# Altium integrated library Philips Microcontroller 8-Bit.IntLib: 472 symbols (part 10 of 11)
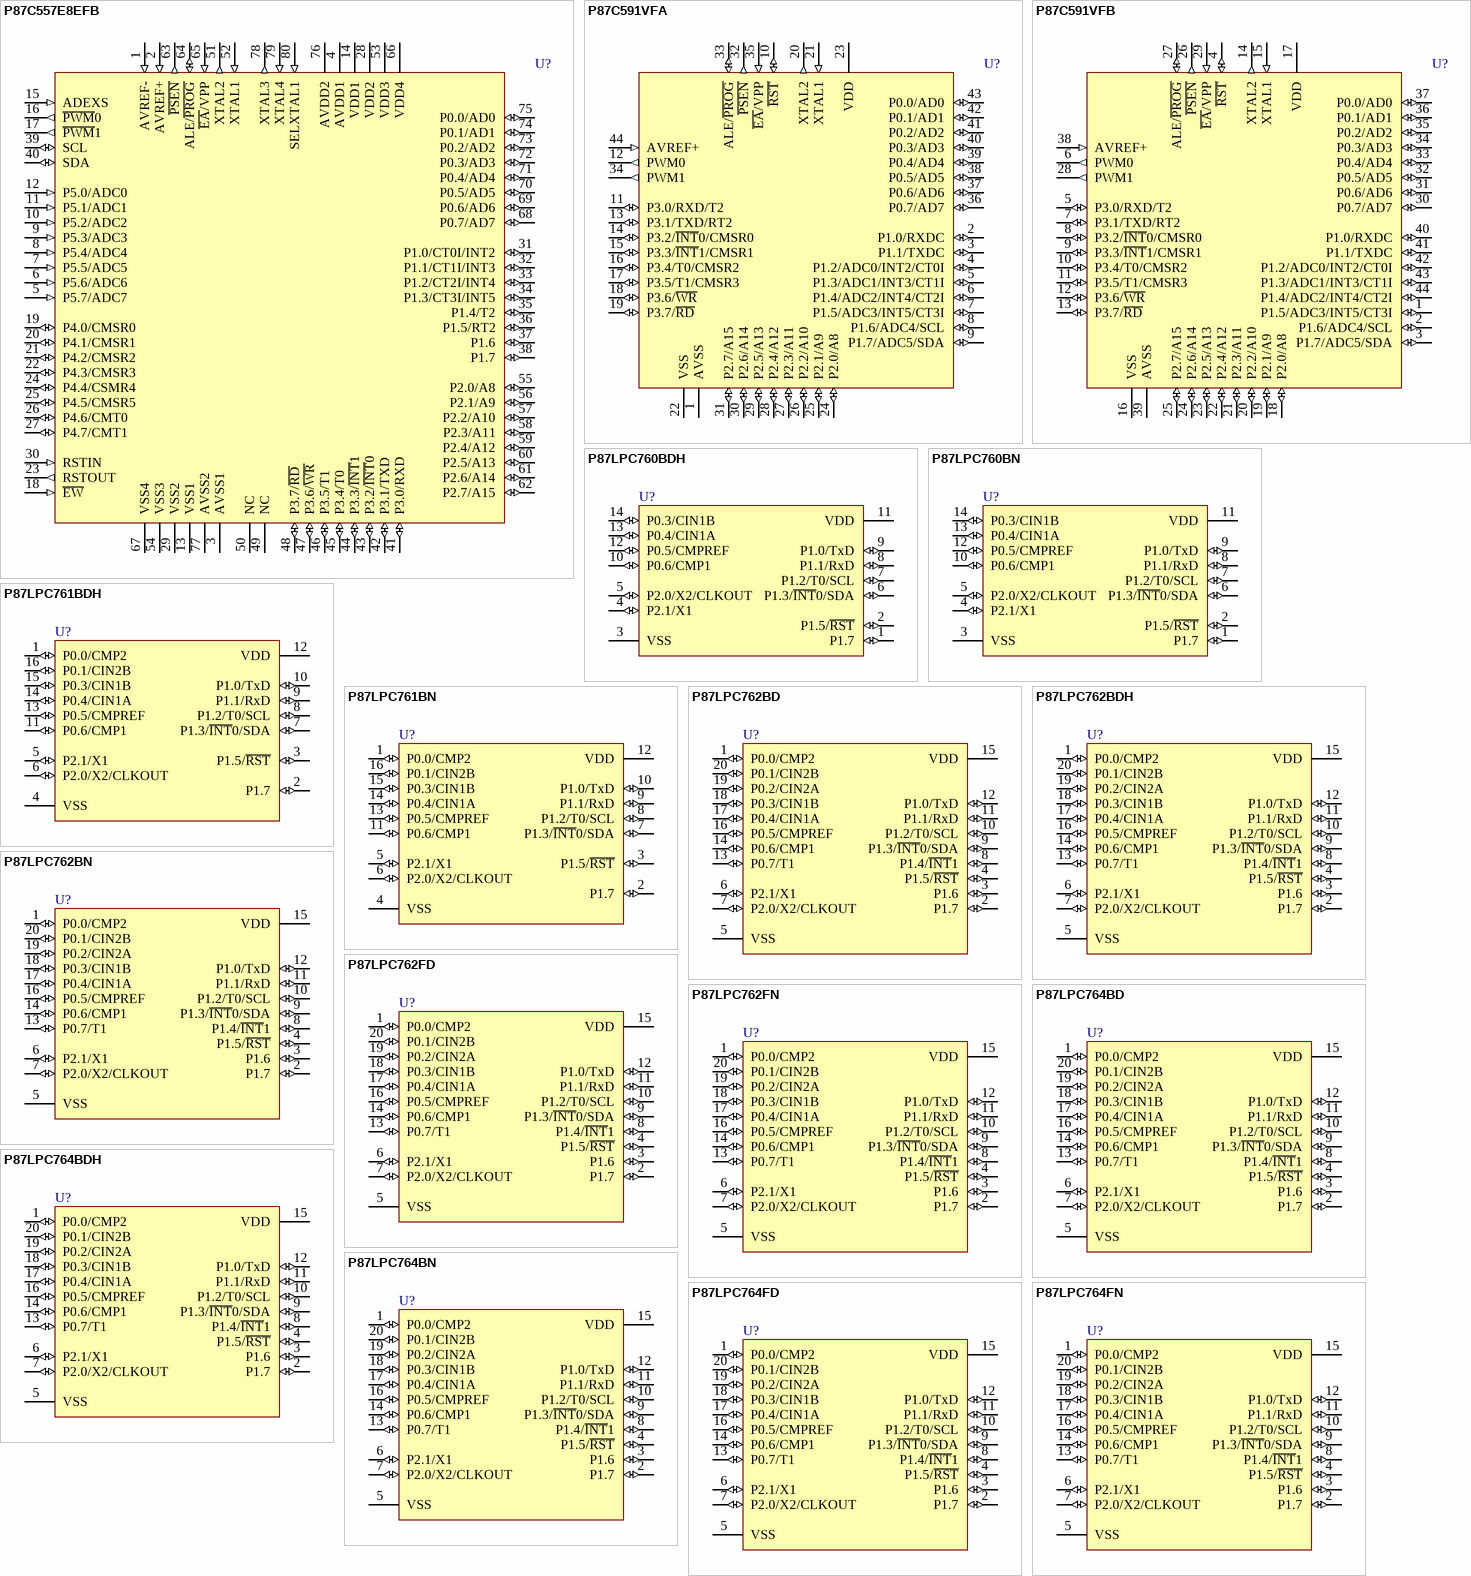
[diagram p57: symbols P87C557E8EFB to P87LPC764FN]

## P87LPC762BN
designator U?
Low Power, Low Price, Low Pin Count (20 pin) Microcontroller with 2 kB OTP
footprint SOT146-1 (DIP; 20 Leads; Row Spacing 7.62 mm; Pitch 2.54 mm)
pins: 1 P0.0/CMP2 (io), 2 P1.7 (io), 3 P1.6 (io), 4 P1.5/~{RST} (io), 5 VSS (power), 6 P2.1/X1 (io), 7 P2.0/X2/CLKOUT (io), 8 P1.4/~{INT}1 (io), 9 P1.3/~{INT}0/SDA (io), 10 P1.2/T0/SCL (io), 11 P1.1/RxD (io), 12 P1.0/TxD (io), 13 P0.7/T1 (io), 14 P0.6/CMP1 (io), 15 VDD (power), 16 P0.5/CMPREF (io), 17 P0.4/CIN1A (io), 18 P0.3/CIN1B (io), 19 P0.2/CIN2A (io), 20 P0.1/CIN2B (io)

## P87LPC762FD
designator U?
Low Power, Low Price, Low Pin Count (20 pin) Microcontroller with 2 kB OTP
footprint SOT163-1_N (SOIC, 20-Leads, Body 12.8x7.5mm, Pitch 1.27mm, IPC Medium Density)
footprint SOT163-1_L (SOIC, 20-Leads, Body 12.8x7.5mm, Pitch 1.27mm, IPC High Density)
footprint SOT163-1_M (SOIC, 20-Leads, Body 12.8x7.5mm, Pitch 1.27mm, IPC Low Density)
pins: 1 P0.0/CMP2 (io), 2 P1.7 (io), 3 P1.6 (io), 4 P1.5/~{RST} (io), 5 VSS (power), 6 P2.1/X1 (io), 7 P2.0/X2/CLKOUT (io), 8 P1.4/~{INT}1 (io), 9 P1.3/~{INT}0/SDA (io), 10 P1.2/T0/SCL (io), 11 P1.1/RxD (io), 12 P1.0/TxD (io), 13 P0.7/T1 (io), 14 P0.6/CMP1 (io), 15 VDD (power), 16 P0.5/CMPREF (io), 17 P0.4/CIN1A (io), 18 P0.3/CIN1B (io), 19 P0.2/CIN2A (io), 20 P0.1/CIN2B (io)

## P87LPC762FN
designator U?
Low Power, Low Price, Low Pin Count (20 pin) Microcontroller with 2 kB OTP
footprint SOT146-1 (DIP; 20 Leads; Row Spacing 7.62 mm; Pitch 2.54 mm)
pins: 1 P0.0/CMP2 (io), 2 P1.7 (io), 3 P1.6 (io), 4 P1.5/~{RST} (io), 5 VSS (power), 6 P2.1/X1 (io), 7 P2.0/X2/CLKOUT (io), 8 P1.4/~{INT}1 (io), 9 P1.3/~{INT}0/SDA (io), 10 P1.2/T0/SCL (io), 11 P1.1/RxD (io), 12 P1.0/TxD (io), 13 P0.7/T1 (io), 14 P0.6/CMP1 (io), 15 VDD (power), 16 P0.5/CMPREF (io), 17 P0.4/CIN1A (io), 18 P0.3/CIN1B (io), 19 P0.2/CIN2A (io), 20 P0.1/CIN2B (io)

## P87LPC764BD
designator U?
Low Power, Low Price, Low Pin Count (20 pin) Microcontroller with 4 kB OTP
footprint SOT163-1_N (SOIC, 20-Leads, Body 12.8x7.5mm, Pitch 1.27mm, IPC Medium Density)
footprint SOT163-1_L (SOIC, 20-Leads, Body 12.8x7.5mm, Pitch 1.27mm, IPC High Density)
footprint SOT163-1_M (SOIC, 20-Leads, Body 12.8x7.5mm, Pitch 1.27mm, IPC Low Density)
pins: 1 P0.0/CMP2 (io), 2 P1.7 (io), 3 P1.6 (io), 4 P1.5/~{RST} (io), 5 VSS (power), 6 P2.1/X1 (io), 7 P2.0/X2/CLKOUT (io), 8 P1.4/~{INT}1 (io), 9 P1.3/~{INT}0/SDA (io), 10 P1.2/T0/SCL (io), 11 P1.1/RxD (io), 12 P1.0/TxD (io), 13 P0.7/T1 (io), 14 P0.6/CMP1 (io), 15 VDD (power), 16 P0.5/CMPREF (io), 17 P0.4/CIN1A (io), 18 P0.3/CIN1B (io), 19 P0.2/CIN2A (io), 20 P0.1/CIN2B (io)

## P87LPC764BDH
designator U?
Low Power, Low Price, Low Pin Count (20 pin) Microcontroller with 4 kB OTP
footprint SOT360-1 (Shrink Small Outline; 20 Leads; Body Width 4.4 mm; Pitch 0.65 mm)
pins: 1 P0.0/CMP2 (io), 2 P1.7 (io), 3 P1.6 (io), 4 P1.5/~{RST} (io), 5 VSS (power), 6 P2.1/X1 (io), 7 P2.0/X2/CLKOUT (io), 8 P1.4/~{INT}1 (io), 9 P1.3/~{INT}0/SDA (io), 10 P1.2/T0/SCL (io), 11 P1.1/RxD (io), 12 P1.0/TxD (io), 13 P0.7/T1 (io), 14 P0.6/CMP1 (io), 15 VDD (power), 16 P0.5/CMPREF (io), 17 P0.4/CIN1A (io), 18 P0.3/CIN1B (io), 19 P0.2/CIN2A (io), 20 P0.1/CIN2B (io)

## P87LPC764BN
designator U?
Low Power, Low Price, Low Pin Count (20 pin) Microcontroller with 4 kB OTP
footprint SOT146-1 (DIP; 20 Leads; Row Spacing 7.62 mm; Pitch 2.54 mm)
pins: 1 P0.0/CMP2 (io), 2 P1.7 (io), 3 P1.6 (io), 4 P1.5/~{RST} (io), 5 VSS (power), 6 P2.1/X1 (io), 7 P2.0/X2/CLKOUT (io), 8 P1.4/~{INT}1 (io), 9 P1.3/~{INT}0/SDA (io), 10 P1.2/T0/SCL (io), 11 P1.1/RxD (io), 12 P1.0/TxD (io), 13 P0.7/T1 (io), 14 P0.6/CMP1 (io), 15 VDD (power), 16 P0.5/CMPREF (io), 17 P0.4/CIN1A (io), 18 P0.3/CIN1B (io), 19 P0.2/CIN2A (io), 20 P0.1/CIN2B (io)

## P87LPC764FD
designator U?
Low Power, Low Price, Low Pin Count (20 pin) Microcontroller with 4 kB OTP
footprint SOT163-1_N (SOIC, 20-Leads, Body 12.8x7.5mm, Pitch 1.27mm, IPC Medium Density)
footprint SOT163-1_L (SOIC, 20-Leads, Body 12.8x7.5mm, Pitch 1.27mm, IPC High Density)
footprint SOT163-1_M (SOIC, 20-Leads, Body 12.8x7.5mm, Pitch 1.27mm, IPC Low Density)
pins: 1 P0.0/CMP2 (io), 2 P1.7 (io), 3 P1.6 (io), 4 P1.5/~{RST} (io), 5 VSS (power), 6 P2.1/X1 (io), 7 P2.0/X2/CLKOUT (io), 8 P1.4/~{INT}1 (io), 9 P1.3/~{INT}0/SDA (io), 10 P1.2/T0/SCL (io), 11 P1.1/RxD (io), 12 P1.0/TxD (io), 13 P0.7/T1 (io), 14 P0.6/CMP1 (io), 15 VDD (power), 16 P0.5/CMPREF (io), 17 P0.4/CIN1A (io), 18 P0.3/CIN1B (io), 19 P0.2/CIN2A (io), 20 P0.1/CIN2B (io)

## P87LPC764FN
designator U?
Low Power, Low Price, Low Pin Count (20 pin) Microcontroller with 4 kB OTP
footprint SOT146-1 (DIP; 20 Leads; Row Spacing 7.62 mm; Pitch 2.54 mm)
pins: 1 P0.0/CMP2 (io), 2 P1.7 (io), 3 P1.6 (io), 4 P1.5/~{RST} (io), 5 VSS (power), 6 P2.1/X1 (io), 7 P2.0/X2/CLKOUT (io), 8 P1.4/~{INT}1 (io), 9 P1.3/~{INT}0/SDA (io), 10 P1.2/T0/SCL (io), 11 P1.1/RxD (io), 12 P1.0/TxD (io), 13 P0.7/T1 (io), 14 P0.6/CMP1 (io), 15 VDD (power), 16 P0.5/CMPREF (io), 17 P0.4/CIN1A (io), 18 P0.3/CIN1B (io), 19 P0.2/CIN2A (io), 20 P0.1/CIN2B (io)

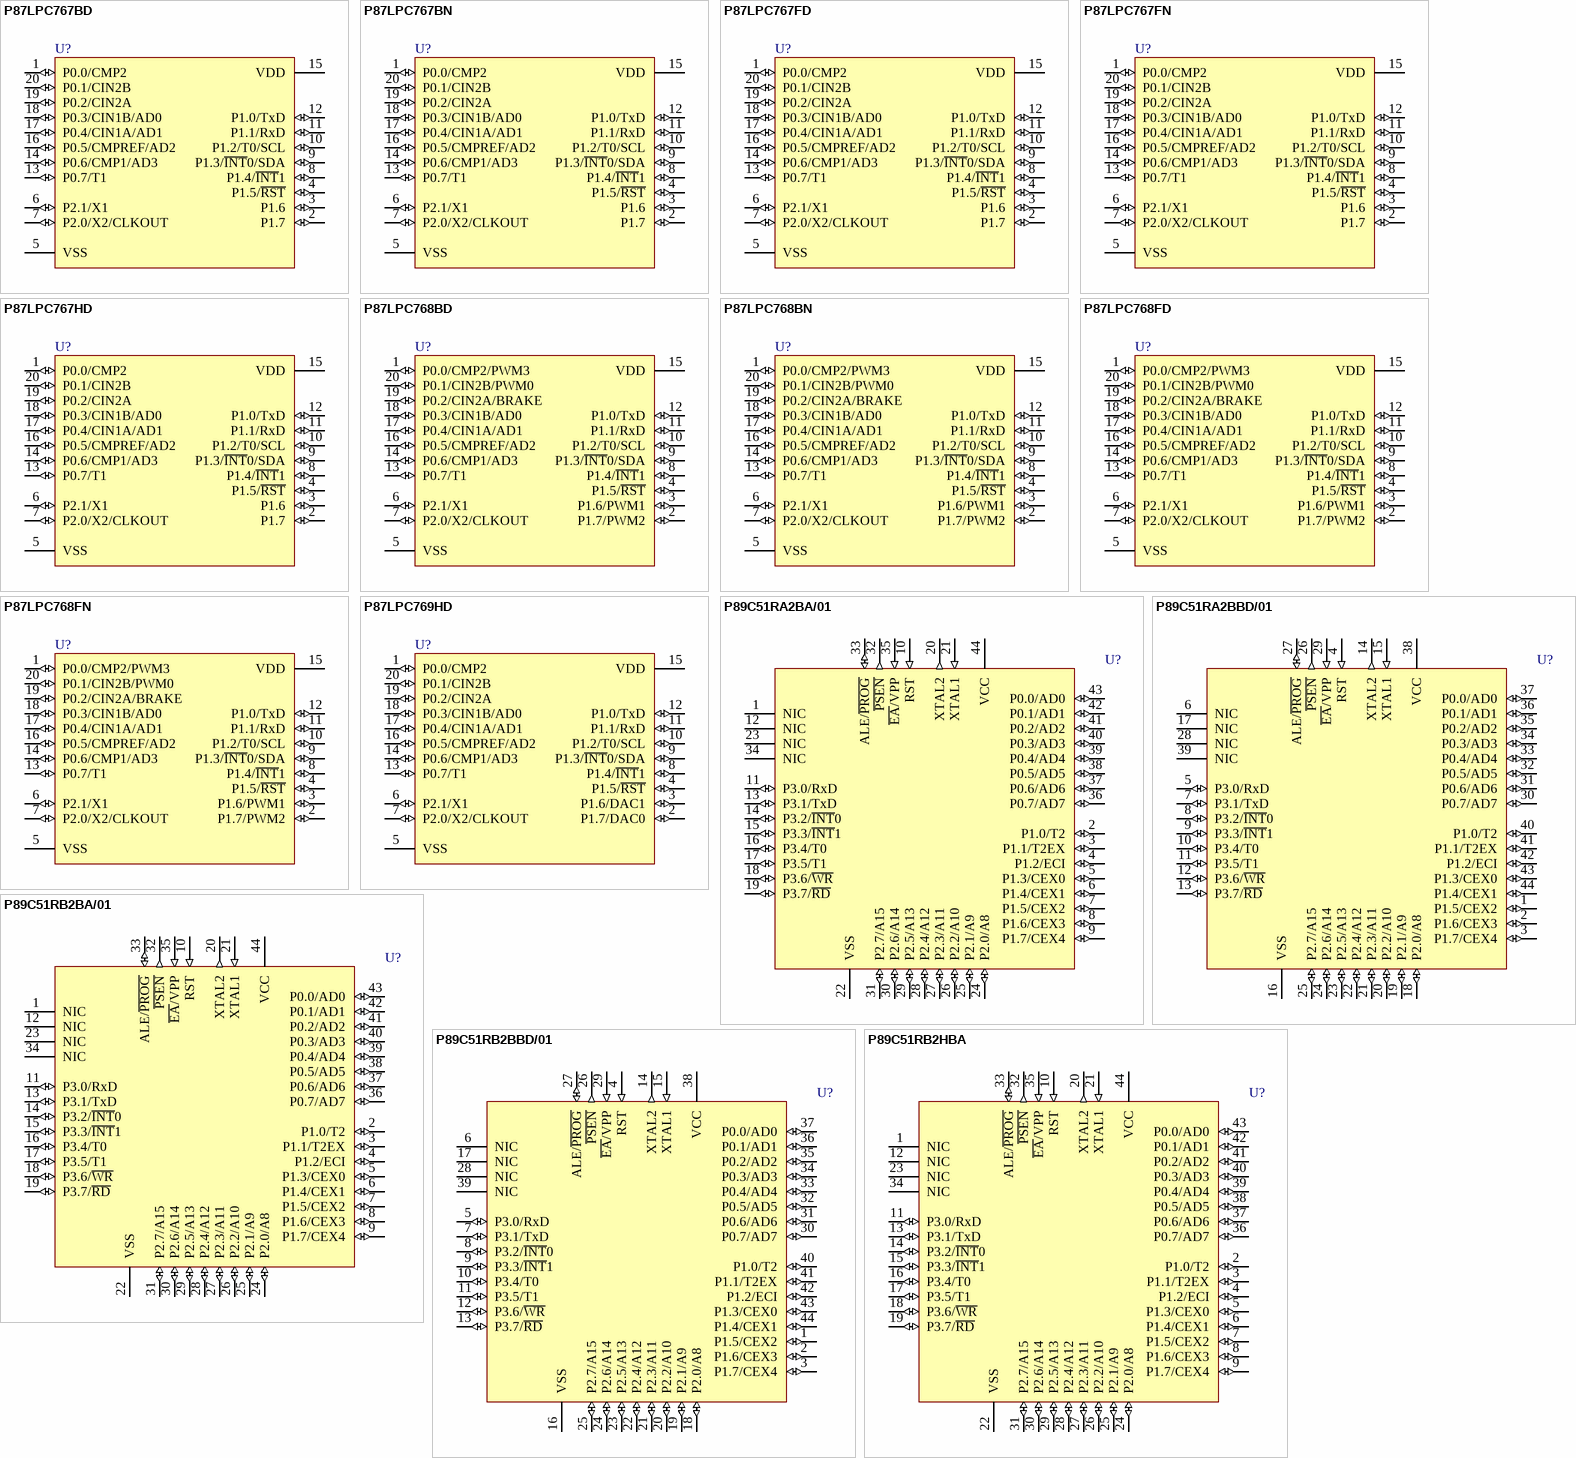
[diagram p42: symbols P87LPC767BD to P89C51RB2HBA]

## P87LPC767BD
designator U?
Low Power, Low Price, Low Pin Count (20 pin) Microcontroller with 4 kB OTP and 8-Bit A/D Converter
footprint SOT163-1_N (SOIC, 20-Leads, Body 12.8x7.5mm, Pitch 1.27mm, IPC Medium Density)
footprint SOT163-1_L (SOIC, 20-Leads, Body 12.8x7.5mm, Pitch 1.27mm, IPC High Density)
footprint SOT163-1_M (SOIC, 20-Leads, Body 12.8x7.5mm, Pitch 1.27mm, IPC Low Density)
pins: 1 P0.0/CMP2 (io), 2 P1.7 (io), 3 P1.6 (io), 4 P1.5/~{RST} (io), 5 VSS (power), 6 P2.1/X1 (io), 7 P2.0/X2/CLKOUT (io), 8 P1.4/~{INT}1 (io), 9 P1.3/~{INT}0/SDA (io), 10 P1.2/T0/SCL (io), 11 P1.1/RxD (io), 12 P1.0/TxD (io), 13 P0.7/T1 (io), 14 P0.6/CMP1/AD3 (io), 15 VDD (power), 16 P0.5/CMPREF/AD2 (io), 17 P0.4/CIN1A/AD1 (io), 18 P0.3/CIN1B/AD0 (io), 19 P0.2/CIN2A (io), 20 P0.1/CIN2B (io)

## P87LPC767BN
designator U?
Low Power, Low Price, Low Pin Count (20 pin) Microcontroller with 4 kB OTP and 8-Bit A/D Converter
footprint SOT146-1 (DIP; 20 Leads; Row Spacing 7.62 mm; Pitch 2.54 mm)
pins: 1 P0.0/CMP2 (io), 2 P1.7 (io), 3 P1.6 (io), 4 P1.5/~{RST} (io), 5 VSS (power), 6 P2.1/X1 (io), 7 P2.0/X2/CLKOUT (io), 8 P1.4/~{INT}1 (io), 9 P1.3/~{INT}0/SDA (io), 10 P1.2/T0/SCL (io), 11 P1.1/RxD (io), 12 P1.0/TxD (io), 13 P0.7/T1 (io), 14 P0.6/CMP1/AD3 (io), 15 VDD (power), 16 P0.5/CMPREF/AD2 (io), 17 P0.4/CIN1A/AD1 (io), 18 P0.3/CIN1B/AD0 (io), 19 P0.2/CIN2A (io), 20 P0.1/CIN2B (io)

## P87LPC767FD
designator U?
Low Power, Low Price, Low Pin Count (20 pin) Microcontroller with 4 kB OTP and 8-Bit A/D Converter
footprint SOT163-1_N (SOIC, 20-Leads, Body 12.8x7.5mm, Pitch 1.27mm, IPC Medium Density)
footprint SOT163-1_L (SOIC, 20-Leads, Body 12.8x7.5mm, Pitch 1.27mm, IPC High Density)
footprint SOT163-1_M (SOIC, 20-Leads, Body 12.8x7.5mm, Pitch 1.27mm, IPC Low Density)
pins: 1 P0.0/CMP2 (io), 2 P1.7 (io), 3 P1.6 (io), 4 P1.5/~{RST} (io), 5 VSS (power), 6 P2.1/X1 (io), 7 P2.0/X2/CLKOUT (io), 8 P1.4/~{INT}1 (io), 9 P1.3/~{INT}0/SDA (io), 10 P1.2/T0/SCL (io), 11 P1.1/RxD (io), 12 P1.0/TxD (io), 13 P0.7/T1 (io), 14 P0.6/CMP1/AD3 (io), 15 VDD (power), 16 P0.5/CMPREF/AD2 (io), 17 P0.4/CIN1A/AD1 (io), 18 P0.3/CIN1B/AD0 (io), 19 P0.2/CIN2A (io), 20 P0.1/CIN2B (io)

## P87LPC767FN
designator U?
Low Power, Low Price, Low Pin Count (20 pin) Microcontroller with 4 kB OTP and 8-Bit A/D Converter
footprint SOT146-1 (DIP; 20 Leads; Row Spacing 7.62 mm; Pitch 2.54 mm)
pins: 1 P0.0/CMP2 (io), 2 P1.7 (io), 3 P1.6 (io), 4 P1.5/~{RST} (io), 5 VSS (power), 6 P2.1/X1 (io), 7 P2.0/X2/CLKOUT (io), 8 P1.4/~{INT}1 (io), 9 P1.3/~{INT}0/SDA (io), 10 P1.2/T0/SCL (io), 11 P1.1/RxD (io), 12 P1.0/TxD (io), 13 P0.7/T1 (io), 14 P0.6/CMP1/AD3 (io), 15 VDD (power), 16 P0.5/CMPREF/AD2 (io), 17 P0.4/CIN1A/AD1 (io), 18 P0.3/CIN1B/AD0 (io), 19 P0.2/CIN2A (io), 20 P0.1/CIN2B (io)

## P87LPC767HD
designator U?
Low Power, Low Price, Low Pin Count (20 pin) Microcontroller with 4 kB OTP and 8-Bit A/D Converter
footprint SOT163-1_N (SOIC, 20-Leads, Body 12.8x7.5mm, Pitch 1.27mm, IPC Medium Density)
footprint SOT163-1_L (SOIC, 20-Leads, Body 12.8x7.5mm, Pitch 1.27mm, IPC High Density)
footprint SOT163-1_M (SOIC, 20-Leads, Body 12.8x7.5mm, Pitch 1.27mm, IPC Low Density)
pins: 1 P0.0/CMP2 (io), 2 P1.7 (io), 3 P1.6 (io), 4 P1.5/~{RST} (io), 5 VSS (power), 6 P2.1/X1 (io), 7 P2.0/X2/CLKOUT (io), 8 P1.4/~{INT}1 (io), 9 P1.3/~{INT}0/SDA (io), 10 P1.2/T0/SCL (io), 11 P1.1/RxD (io), 12 P1.0/TxD (io), 13 P0.7/T1 (io), 14 P0.6/CMP1/AD3 (io), 15 VDD (power), 16 P0.5/CMPREF/AD2 (io), 17 P0.4/CIN1A/AD1 (io), 18 P0.3/CIN1B/AD0 (io), 19 P0.2/CIN2A (io), 20 P0.1/CIN2B (io)

## P87LPC768BD
designator U?
Low Power, Low Price, Low Pin Count (20 pin) Microcontroller with 4 kB OTP 8-Bit A/D, PWM
footprint SOT163-1_N (SOIC, 20-Leads, Body 12.8x7.5mm, Pitch 1.27mm, IPC Medium Density)
footprint SOT163-1_L (SOIC, 20-Leads, Body 12.8x7.5mm, Pitch 1.27mm, IPC High Density)
footprint SOT163-1_M (SOIC, 20-Leads, Body 12.8x7.5mm, Pitch 1.27mm, IPC Low Density)
pins: 1 P0.0/CMP2/PWM3 (io), 2 P1.7/PWM2 (io), 3 P1.6/PWM1 (io), 4 P1.5/~{RST} (io), 5 VSS (power), 6 P2.1/X1 (io), 7 P2.0/X2/CLKOUT (io), 8 P1.4/~{INT}1 (io), 9 P1.3/~{INT}0/SDA (io), 10 P1.2/T0/SCL (io), 11 P1.1/RxD (io), 12 P1.0/TxD (io), 13 P0.7/T1 (io), 14 P0.6/CMP1/AD3 (io), 15 VDD (power), 16 P0.5/CMPREF/AD2 (io), 17 P0.4/CIN1A/AD1 (io), 18 P0.3/CIN1B/AD0 (io), 19 P0.2/CIN2A/BRAKE (io), 20 P0.1/CIN2B/PWM0 (io)

## P87LPC768BN
designator U?
Low Power, Low Price, Low Pin Count (20 pin) Microcontroller with 4 kB OTP 8-Bit A/D, PWM
footprint SOT146-1 (DIP; 20 Leads; Row Spacing 7.62 mm; Pitch 2.54 mm)
pins: 1 P0.0/CMP2/PWM3 (io), 2 P1.7/PWM2 (io), 3 P1.6/PWM1 (io), 4 P1.5/~{RST} (io), 5 VSS (power), 6 P2.1/X1 (io), 7 P2.0/X2/CLKOUT (io), 8 P1.4/~{INT}1 (io), 9 P1.3/~{INT}0/SDA (io), 10 P1.2/T0/SCL (io), 11 P1.1/RxD (io), 12 P1.0/TxD (io), 13 P0.7/T1 (io), 14 P0.6/CMP1/AD3 (io), 15 VDD (power), 16 P0.5/CMPREF/AD2 (io), 17 P0.4/CIN1A/AD1 (io), 18 P0.3/CIN1B/AD0 (io), 19 P0.2/CIN2A/BRAKE (io), 20 P0.1/CIN2B/PWM0 (io)

## P87LPC768FD
designator U?
Low Power, Low Price, Low Pin Count (20 pin) Microcontroller with 4 kB OTP 8-Bit A/D, PWM
footprint SOT163-1_N (SOIC, 20-Leads, Body 12.8x7.5mm, Pitch 1.27mm, IPC Medium Density)
footprint SOT163-1_L (SOIC, 20-Leads, Body 12.8x7.5mm, Pitch 1.27mm, IPC High Density)
footprint SOT163-1_M (SOIC, 20-Leads, Body 12.8x7.5mm, Pitch 1.27mm, IPC Low Density)
pins: 1 P0.0/CMP2/PWM3 (io), 2 P1.7/PWM2 (io), 3 P1.6/PWM1 (io), 4 P1.5/~{RST} (io), 5 VSS (power), 6 P2.1/X1 (io), 7 P2.0/X2/CLKOUT (io), 8 P1.4/~{INT}1 (io), 9 P1.3/~{INT}0/SDA (io), 10 P1.2/T0/SCL (io), 11 P1.1/RxD (io), 12 P1.0/TxD (io), 13 P0.7/T1 (io), 14 P0.6/CMP1/AD3 (io), 15 VDD (power), 16 P0.5/CMPREF/AD2 (io), 17 P0.4/CIN1A/AD1 (io), 18 P0.3/CIN1B/AD0 (io), 19 P0.2/CIN2A/BRAKE (io), 20 P0.1/CIN2B/PWM0 (io)

## P87LPC768FN
designator U?
Low Power, Low Price, Low Pin Count (20 pin) Microcontroller with 4 kB OTP 8-Bit A/D, PWM
footprint SOT146-1 (DIP; 20 Leads; Row Spacing 7.62 mm; Pitch 2.54 mm)
pins: 1 P0.0/CMP2/PWM3 (io), 2 P1.7/PWM2 (io), 3 P1.6/PWM1 (io), 4 P1.5/~{RST} (io), 5 VSS (power), 6 P2.1/X1 (io), 7 P2.0/X2/CLKOUT (io), 8 P1.4/~{INT}1 (io), 9 P1.3/~{INT}0/SDA (io), 10 P1.2/T0/SCL (io), 11 P1.1/RxD (io), 12 P1.0/TxD (io), 13 P0.7/T1 (io), 14 P0.6/CMP1/AD3 (io), 15 VDD (power), 16 P0.5/CMPREF/AD2 (io), 17 P0.4/CIN1A/AD1 (io), 18 P0.3/CIN1B/AD0 (io), 19 P0.2/CIN2A/BRAKE (io), 20 P0.1/CIN2B/PWM0 (io)

## P87LPC769HD
designator U?
Low Power, Low Price, Low Pin Count (20 pin) Microcontroller with 4 kB OTP 8-Bit A/D, and DAC
footprint SOT163-1_N (SOIC, 20-Leads, Body 12.8x7.5mm, Pitch 1.27mm, IPC Medium Density)
footprint SOT163-1_L (SOIC, 20-Leads, Body 12.8x7.5mm, Pitch 1.27mm, IPC High Density)
footprint SOT163-1_M (SOIC, 20-Leads, Body 12.8x7.5mm, Pitch 1.27mm, IPC Low Density)
pins: 1 P0.0/CMP2 (io), 2 P1.7/DAC0 (io), 3 P1.6/DAC1 (io), 4 P1.5/~{RST} (io), 5 VSS (power), 6 P2.1/X1 (io), 7 P2.0/X2/CLKOUT (io), 8 P1.4/~{INT}1 (io), 9 P1.3/~{INT}0/SDA (io), 10 P1.2/T0/SCL (io), 11 P1.1/RxD (io), 12 P1.0/TxD (io), 13 P0.7/T1 (io), 14 P0.6/CMP1/AD3 (io), 15 VDD (power), 16 P0.5/CMPREF/AD2 (io), 17 P0.4/CIN1A/AD1 (io), 18 P0.3/CIN1B/AD0 (io), 19 P0.2/CIN2A (io), 20 P0.1/CIN2B (io)

## P89C51RA2BA/01
designator U?
80C51 8-Bit Flash Microcontroller Family, 8 kB ISP/IAP Flash with 512 B RAM.
footprint SOT187-2_N (Leaded Chip Carrier, 44-Leads, Body 16.6x16.6mm, Pitch 1.27mm, IPC Medium Density)
footprint SOT187-2_L (Leaded Chip Carrier, 44-Leads, Body 16.6x16.6mm, Pitch 1.27mm, IPC High Density)
footprint SOT187-2_M (Leaded Chip Carrier, 44-Leads, Body 16.6x16.6mm, Pitch 1.27mm, IPC Low Density)
pins: 1 NIC, 2 P1.0/T2 (io), 3 P1.1/T2EX (io), 4 P1.2/ECI (io), 5 P1.3/CEX0 (io), 6 P1.4/CEX1 (io), 7 P1.5/CEX2 (io), 8 P1.6/CEX3 (io), 9 P1.7/CEX4 (io), 10 RST (in), 11 P3.0/RxD (io), 12 NIC, 13 P3.1/TxD (io), 14 P3.2/~{INT}0 (io), 15 P3.3/~{INT}1 (io), 16 P3.4/T0 (io), 17 P3.5/T1 (io), 18 P3.6/~{WR} (io), 19 P3.7/~{RD} (io), 20 XTAL2 (out), 21 XTAL1 (in), 22 VSS (power), 23 NIC, 24 P2.0/A8 (io), 25 P2.1/A9 (io), 26 P2.2/A10 (io), 27 P2.3/A11 (io), 28 P2.4/A12 (io), 29 P2.5/A13 (io), 30 P2.6/A14 (io), 31 P2.7/A15 (io), 32 ~{PSEN} (out), 33 ALE/~{PROG} (io), 34 NIC, 35 ~{EA}/VPP (in), 36 P0.7/AD7 (io), 37 P0.6/AD6 (io), 38 P0.5/AD5 (io), 39 P0.4/AD4 (io), 40 P0.3/AD3 (io), 41 P0.2/AD2 (io), 42 P0.1/AD1 (io), 43 P0.0/AD0 (io), 44 VCC (power)

## P89C51RA2BBD/01
designator U?
80C51 8-Bit Flash Microcontroller Family, 8 kB ISP/IAP Flash with 512 B RAM.
footprint SOT389-1_N (Thin QFP, 44-Leads, Body 10x10mm, Pitch 0.8mm, IPC Medium Density)
footprint SOT389-1_L (Thin QFP, 44-Leads, Body 10x10mm, Pitch 0.8mm, IPC High Density)
footprint SOT389-1_M (Thin QFP, 44-Leads, Body 10x10mm, Pitch 0.8mm, IPC Low Density)
pins: 1 P1.5/CEX2 (io), 2 P1.6/CEX3 (io), 3 P1.7/CEX4 (io), 4 RST (in), 5 P3.0/RxD (io), 6 NIC, 7 P3.1/TxD (io), 8 P3.2/~{INT}0 (io), 9 P3.3/~{INT}1 (io), 10 P3.4/T0 (io), 11 P3.5/T1 (io), 12 P3.6/~{WR} (io), 13 P3.7/~{RD} (io), 14 XTAL2 (out), 15 XTAL1 (in), 16 VSS (power), 17 NIC, 18 P2.0/A8 (io), 19 P2.1/A9 (io), 20 P2.2/A10 (io), 21 P2.3/A11 (io), 22 P2.4/A12 (io), 23 P2.5/A13 (io), 24 P2.6/A14 (io), 25 P2.7/A15 (io), 26 ~{PSEN} (out), 27 ALE/~{PROG} (io), 28 NIC, 29 ~{EA}/VPP (in), 30 P0.7/AD7 (io), 31 P0.6/AD6 (io), 32 P0.5/AD5 (io), 33 P0.4/AD4 (io), 34 P0.3/AD3 (io), 35 P0.2/AD2 (io), 36 P0.1/AD1 (io), 37 P0.0/AD0 (io), 38 VCC (power), 39 NIC, 40 P1.0/T2 (io), 41 P1.1/T2EX (io), 42 P1.2/ECI (io), 43 P1.3/CEX0 (io), 44 P1.4/CEX1 (io)

## P89C51RB2BA/01
designator U?
80C51 8-Bit Flash Microcontroller Family, 16 kB ISP/IAP Flash with 512 B RAM.
footprint SOT187-2_N (Leaded Chip Carrier, 44-Leads, Body 16.6x16.6mm, Pitch 1.27mm, IPC Medium Density)
footprint SOT187-2_L (Leaded Chip Carrier, 44-Leads, Body 16.6x16.6mm, Pitch 1.27mm, IPC High Density)
footprint SOT187-2_M (Leaded Chip Carrier, 44-Leads, Body 16.6x16.6mm, Pitch 1.27mm, IPC Low Density)
pins: 1 NIC, 2 P1.0/T2 (io), 3 P1.1/T2EX (io), 4 P1.2/ECI (io), 5 P1.3/CEX0 (io), 6 P1.4/CEX1 (io), 7 P1.5/CEX2 (io), 8 P1.6/CEX3 (io), 9 P1.7/CEX4 (io), 10 RST (in), 11 P3.0/RxD (io), 12 NIC, 13 P3.1/TxD (io), 14 P3.2/~{INT}0 (io), 15 P3.3/~{INT}1 (io), 16 P3.4/T0 (io), 17 P3.5/T1 (io), 18 P3.6/~{WR} (io), 19 P3.7/~{RD} (io), 20 XTAL2 (out), 21 XTAL1 (in), 22 VSS (power), 23 NIC, 24 P2.0/A8 (io), 25 P2.1/A9 (io), 26 P2.2/A10 (io), 27 P2.3/A11 (io), 28 P2.4/A12 (io), 29 P2.5/A13 (io), 30 P2.6/A14 (io), 31 P2.7/A15 (io), 32 ~{PSEN} (out), 33 ALE/~{PROG} (io), 34 NIC, 35 ~{EA}/VPP (in), 36 P0.7/AD7 (io), 37 P0.6/AD6 (io), 38 P0.5/AD5 (io), 39 P0.4/AD4 (io), 40 P0.3/AD3 (io), 41 P0.2/AD2 (io), 42 P0.1/AD1 (io), 43 P0.0/AD0 (io), 44 VCC (power)

## P89C51RB2BBD/01
designator U?
80C51 8-Bit Flash Microcontroller Family, 16 kB ISP/IAP Flash with 512 B RAM.
footprint SOT389-1_N (Thin QFP, 44-Leads, Body 10x10mm, Pitch 0.8mm, IPC Medium Density)
footprint SOT389-1_L (Thin QFP, 44-Leads, Body 10x10mm, Pitch 0.8mm, IPC High Density)
footprint SOT389-1_M (Thin QFP, 44-Leads, Body 10x10mm, Pitch 0.8mm, IPC Low Density)
pins: 1 P1.5/CEX2 (io), 2 P1.6/CEX3 (io), 3 P1.7/CEX4 (io), 4 RST (in), 5 P3.0/RxD (io), 6 NIC, 7 P3.1/TxD (io), 8 P3.2/~{INT}0 (io), 9 P3.3/~{INT}1 (io), 10 P3.4/T0 (io), 11 P3.5/T1 (io), 12 P3.6/~{WR} (io), 13 P3.7/~{RD} (io), 14 XTAL2 (out), 15 XTAL1 (in), 16 VSS (power), 17 NIC, 18 P2.0/A8 (io), 19 P2.1/A9 (io), 20 P2.2/A10 (io), 21 P2.3/A11 (io), 22 P2.4/A12 (io), 23 P2.5/A13 (io), 24 P2.6/A14 (io), 25 P2.7/A15 (io), 26 ~{PSEN} (out), 27 ALE/~{PROG} (io), 28 NIC, 29 ~{EA}/VPP (in), 30 P0.7/AD7 (io), 31 P0.6/AD6 (io), 32 P0.5/AD5 (io), 33 P0.4/AD4 (io), 34 P0.3/AD3 (io), 35 P0.2/AD2 (io), 36 P0.1/AD1 (io), 37 P0.0/AD0 (io), 38 VCC (power), 39 NIC, 40 P1.0/T2 (io), 41 P1.1/T2EX (io), 42 P1.2/ECI (io), 43 P1.3/CEX0 (io), 44 P1.4/CEX1 (io)

## P89C51RB2HBA
designator U?
80C51 8-Bit Flash Microcontroller Family, 16 kB ISP/IAP Flash with 512 B RAM.
footprint SOT187-2_N (Leaded Chip Carrier, 44-Leads, Body 16.6x16.6mm, Pitch 1.27mm, IPC Medium Density)
footprint SOT187-2_L (Leaded Chip Carrier, 44-Leads, Body 16.6x16.6mm, Pitch 1.27mm, IPC High Density)
footprint SOT187-2_M (Leaded Chip Carrier, 44-Leads, Body 16.6x16.6mm, Pitch 1.27mm, IPC Low Density)
pins: 1 NIC, 2 P1.0/T2 (io), 3 P1.1/T2EX (io), 4 P1.2/ECI (io), 5 P1.3/CEX0 (io), 6 P1.4/CEX1 (io), 7 P1.5/CEX2 (io), 8 P1.6/CEX3 (io), 9 P1.7/CEX4 (io), 10 RST (in), 11 P3.0/RxD (io), 12 NIC, 13 P3.1/TxD (io), 14 P3.2/~{INT}0 (io), 15 P3.3/~{INT}1 (io), 16 P3.4/T0 (io), 17 P3.5/T1 (io), 18 P3.6/~{WR} (io), 19 P3.7/~{RD} (io), 20 XTAL2 (out), 21 XTAL1 (in), 22 VSS (power), 23 NIC, 24 P2.0/A8 (io), 25 P2.1/A9 (io), 26 P2.2/A10 (io), 27 P2.3/A11 (io), 28 P2.4/A12 (io), 29 P2.5/A13 (io), 30 P2.6/A14 (io), 31 P2.7/A15 (io), 32 ~{PSEN} (out), 33 ALE/~{PROG} (io), 34 NIC, 35 ~{EA}/VPP (in), 36 P0.7/AD7 (io), 37 P0.6/AD6 (io), 38 P0.5/AD5 (io), 39 P0.4/AD4 (io), 40 P0.3/AD3 (io), 41 P0.2/AD2 (io), 42 P0.1/AD1 (io), 43 P0.0/AD0 (io), 44 VCC (power)

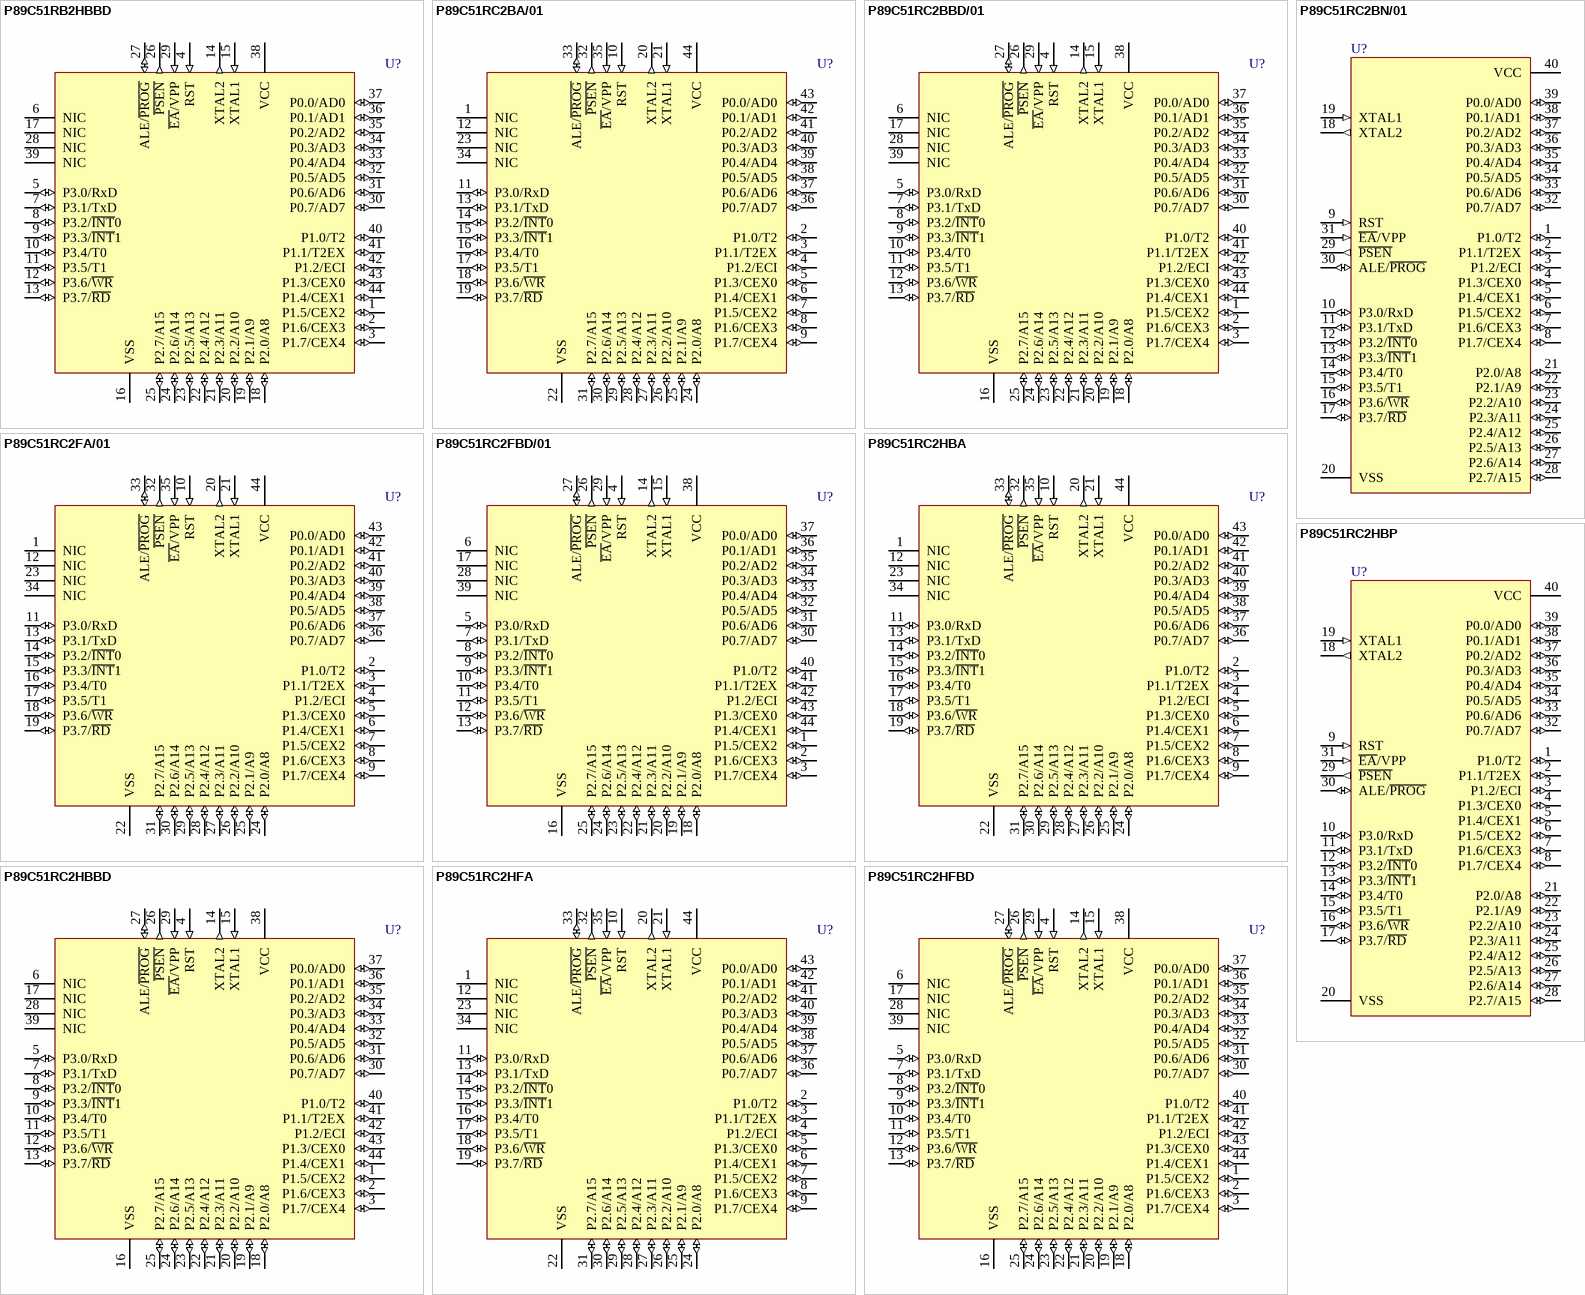
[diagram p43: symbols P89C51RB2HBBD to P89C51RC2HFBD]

## P89C51RB2HBBD
designator U?
80C51 8-Bit Flash Microcontroller Family, 16 kB ISP/IAP Flash with 512 B RAM.
footprint SOT389-1_N (Thin QFP, 44-Leads, Body 10x10mm, Pitch 0.8mm, IPC Medium Density)
footprint SOT389-1_L (Thin QFP, 44-Leads, Body 10x10mm, Pitch 0.8mm, IPC High Density)
footprint SOT389-1_M (Thin QFP, 44-Leads, Body 10x10mm, Pitch 0.8mm, IPC Low Density)
pins: 1 P1.5/CEX2 (io), 2 P1.6/CEX3 (io), 3 P1.7/CEX4 (io), 4 RST (in), 5 P3.0/RxD (io), 6 NIC, 7 P3.1/TxD (io), 8 P3.2/~{INT}0 (io), 9 P3.3/~{INT}1 (io), 10 P3.4/T0 (io), 11 P3.5/T1 (io), 12 P3.6/~{WR} (io), 13 P3.7/~{RD} (io), 14 XTAL2 (out), 15 XTAL1 (in), 16 VSS (power), 17 NIC, 18 P2.0/A8 (io), 19 P2.1/A9 (io), 20 P2.2/A10 (io), 21 P2.3/A11 (io), 22 P2.4/A12 (io), 23 P2.5/A13 (io), 24 P2.6/A14 (io), 25 P2.7/A15 (io), 26 ~{PSEN} (out), 27 ALE/~{PROG} (io), 28 NIC, 29 ~{EA}/VPP (in), 30 P0.7/AD7 (io), 31 P0.6/AD6 (io), 32 P0.5/AD5 (io), 33 P0.4/AD4 (io), 34 P0.3/AD3 (io), 35 P0.2/AD2 (io), 36 P0.1/AD1 (io), 37 P0.0/AD0 (io), 38 VCC (power), 39 NIC, 40 P1.0/T2 (io), 41 P1.1/T2EX (io), 42 P1.2/ECI (io), 43 P1.3/CEX0 (io), 44 P1.4/CEX1 (io)

## P89C51RC2BA/01
designator U?
80C51 8-Bit Flash Microcontroller Family, 32 kB ISP/IAP Flash with 512 B RAM.
footprint SOT187-2_N (Leaded Chip Carrier, 44-Leads, Body 16.6x16.6mm, Pitch 1.27mm, IPC Medium Density)
footprint SOT187-2_L (Leaded Chip Carrier, 44-Leads, Body 16.6x16.6mm, Pitch 1.27mm, IPC High Density)
footprint SOT187-2_M (Leaded Chip Carrier, 44-Leads, Body 16.6x16.6mm, Pitch 1.27mm, IPC Low Density)
pins: 1 NIC, 2 P1.0/T2 (io), 3 P1.1/T2EX (io), 4 P1.2/ECI (io), 5 P1.3/CEX0 (io), 6 P1.4/CEX1 (io), 7 P1.5/CEX2 (io), 8 P1.6/CEX3 (io), 9 P1.7/CEX4 (io), 10 RST (in), 11 P3.0/RxD (io), 12 NIC, 13 P3.1/TxD (io), 14 P3.2/~{INT}0 (io), 15 P3.3/~{INT}1 (io), 16 P3.4/T0 (io), 17 P3.5/T1 (io), 18 P3.6/~{WR} (io), 19 P3.7/~{RD} (io), 20 XTAL2 (out), 21 XTAL1 (in), 22 VSS (power), 23 NIC, 24 P2.0/A8 (io), 25 P2.1/A9 (io), 26 P2.2/A10 (io), 27 P2.3/A11 (io), 28 P2.4/A12 (io), 29 P2.5/A13 (io), 30 P2.6/A14 (io), 31 P2.7/A15 (io), 32 ~{PSEN} (out), 33 ALE/~{PROG} (io), 34 NIC, 35 ~{EA}/VPP (in), 36 P0.7/AD7 (io), 37 P0.6/AD6 (io), 38 P0.5/AD5 (io), 39 P0.4/AD4 (io), 40 P0.3/AD3 (io), 41 P0.2/AD2 (io), 42 P0.1/AD1 (io), 43 P0.0/AD0 (io), 44 VCC (power)

## P89C51RC2BBD/01
designator U?
80C51 8-Bit Flash Microcontroller Family, 32 kB ISP/IAP Flash with 512 B RAM.
footprint SOT389-1_N (Thin QFP, 44-Leads, Body 10x10mm, Pitch 0.8mm, IPC Medium Density)
footprint SOT389-1_L (Thin QFP, 44-Leads, Body 10x10mm, Pitch 0.8mm, IPC High Density)
footprint SOT389-1_M (Thin QFP, 44-Leads, Body 10x10mm, Pitch 0.8mm, IPC Low Density)
pins: 1 P1.5/CEX2 (io), 2 P1.6/CEX3 (io), 3 P1.7/CEX4 (io), 4 RST (in), 5 P3.0/RxD (io), 6 NIC, 7 P3.1/TxD (io), 8 P3.2/~{INT}0 (io), 9 P3.3/~{INT}1 (io), 10 P3.4/T0 (io), 11 P3.5/T1 (io), 12 P3.6/~{WR} (io), 13 P3.7/~{RD} (io), 14 XTAL2 (out), 15 XTAL1 (in), 16 VSS (power), 17 NIC, 18 P2.0/A8 (io), 19 P2.1/A9 (io), 20 P2.2/A10 (io), 21 P2.3/A11 (io), 22 P2.4/A12 (io), 23 P2.5/A13 (io), 24 P2.6/A14 (io), 25 P2.7/A15 (io), 26 ~{PSEN} (out), 27 ALE/~{PROG} (io), 28 NIC, 29 ~{EA}/VPP (in), 30 P0.7/AD7 (io), 31 P0.6/AD6 (io), 32 P0.5/AD5 (io), 33 P0.4/AD4 (io), 34 P0.3/AD3 (io), 35 P0.2/AD2 (io), 36 P0.1/AD1 (io), 37 P0.0/AD0 (io), 38 VCC (power), 39 NIC, 40 P1.0/T2 (io), 41 P1.1/T2EX (io), 42 P1.2/ECI (io), 43 P1.3/CEX0 (io), 44 P1.4/CEX1 (io)

## P89C51RC2BN/01
designator U?
80C51 8-Bit Flash Microcontroller Family, 32 kB ISP/IAP Flash with 512 B RAM.
footprint SOT129-1 (DIP, Plastic; 40 Leads; Row Spacing 15.24 mm; Pitch 2.54 mm)
pins: 1 P1.0/T2 (io), 2 P1.1/T2EX (io), 3 P1.2/ECI (io), 4 P1.3/CEX0 (io), 5 P1.4/CEX1 (io), 6 P1.5/CEX2 (io), 7 P1.6/CEX3 (io), 8 P1.7/CEX4 (io), 9 RST (in), 10 P3.0/RxD (io), 11 P3.1/TxD (io), 12 P3.2/~{INT}0 (io), 13 P3.3/~{INT}1 (io), 14 P3.4/T0 (io), 15 P3.5/T1 (io), 16 P3.6/~{WR} (io), 17 P3.7/~{RD} (io), 18 XTAL2 (out), 19 XTAL1 (in), 20 VSS (power), 21 P2.0/A8 (io), 22 P2.1/A9 (io), 23 P2.2/A10 (io), 24 P2.3/A11 (io), 25 P2.4/A12 (io), 26 P2.5/A13 (io), 27 P2.6/A14 (io), 28 P2.7/A15 (io), 29 ~{PSEN} (out), 30 ALE/~{PROG} (io), 31 ~{EA}/VPP (in), 32 P0.7/AD7 (io), 33 P0.6/AD6 (io), 34 P0.5/AD5 (io), 35 P0.4/AD4 (io), 36 P0.3/AD3 (io), 37 P0.2/AD2 (io), 38 P0.1/AD1 (io), 39 P0.0/AD0 (io), 40 VCC (power)

## P89C51RC2FA/01
designator U?
80C51 8-Bit Flash Microcontroller Family, 32 kB ISP/IAP Flash with 512 B RAM.
footprint SOT187-2_N (Leaded Chip Carrier, 44-Leads, Body 16.6x16.6mm, Pitch 1.27mm, IPC Medium Density)
footprint SOT187-2_L (Leaded Chip Carrier, 44-Leads, Body 16.6x16.6mm, Pitch 1.27mm, IPC High Density)
footprint SOT187-2_M (Leaded Chip Carrier, 44-Leads, Body 16.6x16.6mm, Pitch 1.27mm, IPC Low Density)
pins: 1 NIC, 2 P1.0/T2 (io), 3 P1.1/T2EX (io), 4 P1.2/ECI (io), 5 P1.3/CEX0 (io), 6 P1.4/CEX1 (io), 7 P1.5/CEX2 (io), 8 P1.6/CEX3 (io), 9 P1.7/CEX4 (io), 10 RST (in), 11 P3.0/RxD (io), 12 NIC, 13 P3.1/TxD (io), 14 P3.2/~{INT}0 (io), 15 P3.3/~{INT}1 (io), 16 P3.4/T0 (io), 17 P3.5/T1 (io), 18 P3.6/~{WR} (io), 19 P3.7/~{RD} (io), 20 XTAL2 (out), 21 XTAL1 (in), 22 VSS (power), 23 NIC, 24 P2.0/A8 (io), 25 P2.1/A9 (io), 26 P2.2/A10 (io), 27 P2.3/A11 (io), 28 P2.4/A12 (io), 29 P2.5/A13 (io), 30 P2.6/A14 (io), 31 P2.7/A15 (io), 32 ~{PSEN} (out), 33 ALE/~{PROG} (io), 34 NIC, 35 ~{EA}/VPP (in), 36 P0.7/AD7 (io), 37 P0.6/AD6 (io), 38 P0.5/AD5 (io), 39 P0.4/AD4 (io), 40 P0.3/AD3 (io), 41 P0.2/AD2 (io), 42 P0.1/AD1 (io), 43 P0.0/AD0 (io), 44 VCC (power)

## P89C51RC2FBD/01
designator U?
80C51 8-Bit Flash Microcontroller Family, 32 kB ISP/IAP Flash with 512 B RAM.
footprint SOT389-1_N (Thin QFP, 44-Leads, Body 10x10mm, Pitch 0.8mm, IPC Medium Density)
footprint SOT389-1_L (Thin QFP, 44-Leads, Body 10x10mm, Pitch 0.8mm, IPC High Density)
footprint SOT389-1_M (Thin QFP, 44-Leads, Body 10x10mm, Pitch 0.8mm, IPC Low Density)
pins: 1 P1.5/CEX2 (io), 2 P1.6/CEX3 (io), 3 P1.7/CEX4 (io), 4 RST (in), 5 P3.0/RxD (io), 6 NIC, 7 P3.1/TxD (io), 8 P3.2/~{INT}0 (io), 9 P3.3/~{INT}1 (io), 10 P3.4/T0 (io), 11 P3.5/T1 (io), 12 P3.6/~{WR} (io), 13 P3.7/~{RD} (io), 14 XTAL2 (out), 15 XTAL1 (in), 16 VSS (power), 17 NIC, 18 P2.0/A8 (io), 19 P2.1/A9 (io), 20 P2.2/A10 (io), 21 P2.3/A11 (io), 22 P2.4/A12 (io), 23 P2.5/A13 (io), 24 P2.6/A14 (io), 25 P2.7/A15 (io), 26 ~{PSEN} (out), 27 ALE/~{PROG} (io), 28 NIC, 29 ~{EA}/VPP (in), 30 P0.7/AD7 (io), 31 P0.6/AD6 (io), 32 P0.5/AD5 (io), 33 P0.4/AD4 (io), 34 P0.3/AD3 (io), 35 P0.2/AD2 (io), 36 P0.1/AD1 (io), 37 P0.0/AD0 (io), 38 VCC (power), 39 NIC, 40 P1.0/T2 (io), 41 P1.1/T2EX (io), 42 P1.2/ECI (io), 43 P1.3/CEX0 (io), 44 P1.4/CEX1 (io)

## P89C51RC2HBA
designator U?
80C51 8-Bit Flash Microcontroller Family, 32 kB ISP/IAP Flash with 512 B RAM.
footprint SOT187-2_N (Leaded Chip Carrier, 44-Leads, Body 16.6x16.6mm, Pitch 1.27mm, IPC Medium Density)
footprint SOT187-2_L (Leaded Chip Carrier, 44-Leads, Body 16.6x16.6mm, Pitch 1.27mm, IPC High Density)
footprint SOT187-2_M (Leaded Chip Carrier, 44-Leads, Body 16.6x16.6mm, Pitch 1.27mm, IPC Low Density)
pins: 1 NIC, 2 P1.0/T2 (io), 3 P1.1/T2EX (io), 4 P1.2/ECI (io), 5 P1.3/CEX0 (io), 6 P1.4/CEX1 (io), 7 P1.5/CEX2 (io), 8 P1.6/CEX3 (io), 9 P1.7/CEX4 (io), 10 RST (in), 11 P3.0/RxD (io), 12 NIC, 13 P3.1/TxD (io), 14 P3.2/~{INT}0 (io), 15 P3.3/~{INT}1 (io), 16 P3.4/T0 (io), 17 P3.5/T1 (io), 18 P3.6/~{WR} (io), 19 P3.7/~{RD} (io), 20 XTAL2 (out), 21 XTAL1 (in), 22 VSS (power), 23 NIC, 24 P2.0/A8 (io), 25 P2.1/A9 (io), 26 P2.2/A10 (io), 27 P2.3/A11 (io), 28 P2.4/A12 (io), 29 P2.5/A13 (io), 30 P2.6/A14 (io), 31 P2.7/A15 (io), 32 ~{PSEN} (out), 33 ALE/~{PROG} (io), 34 NIC, 35 ~{EA}/VPP (in), 36 P0.7/AD7 (io), 37 P0.6/AD6 (io), 38 P0.5/AD5 (io), 39 P0.4/AD4 (io), 40 P0.3/AD3 (io), 41 P0.2/AD2 (io), 42 P0.1/AD1 (io), 43 P0.0/AD0 (io), 44 VCC (power)

## P89C51RC2HBBD
designator U?
80C51 8-Bit Flash Microcontroller Family, 32 kB ISP/IAP Flash with 512 B RAM.
footprint SOT389-1_N (Thin QFP, 44-Leads, Body 10x10mm, Pitch 0.8mm, IPC Medium Density)
footprint SOT389-1_L (Thin QFP, 44-Leads, Body 10x10mm, Pitch 0.8mm, IPC High Density)
footprint SOT389-1_M (Thin QFP, 44-Leads, Body 10x10mm, Pitch 0.8mm, IPC Low Density)
pins: 1 P1.5/CEX2 (io), 2 P1.6/CEX3 (io), 3 P1.7/CEX4 (io), 4 RST (in), 5 P3.0/RxD (io), 6 NIC, 7 P3.1/TxD (io), 8 P3.2/~{INT}0 (io), 9 P3.3/~{INT}1 (io), 10 P3.4/T0 (io), 11 P3.5/T1 (io), 12 P3.6/~{WR} (io), 13 P3.7/~{RD} (io), 14 XTAL2 (out), 15 XTAL1 (in), 16 VSS (power), 17 NIC, 18 P2.0/A8 (io), 19 P2.1/A9 (io), 20 P2.2/A10 (io), 21 P2.3/A11 (io), 22 P2.4/A12 (io), 23 P2.5/A13 (io), 24 P2.6/A14 (io), 25 P2.7/A15 (io), 26 ~{PSEN} (out), 27 ALE/~{PROG} (io), 28 NIC, 29 ~{EA}/VPP (in), 30 P0.7/AD7 (io), 31 P0.6/AD6 (io), 32 P0.5/AD5 (io), 33 P0.4/AD4 (io), 34 P0.3/AD3 (io), 35 P0.2/AD2 (io), 36 P0.1/AD1 (io), 37 P0.0/AD0 (io), 38 VCC (power), 39 NIC, 40 P1.0/T2 (io), 41 P1.1/T2EX (io), 42 P1.2/ECI (io), 43 P1.3/CEX0 (io), 44 P1.4/CEX1 (io)

## P89C51RC2HBP
designator U?
80C51 8-Bit Flash Microcontroller Family, 32 kB ISP/IAP Flash with 512 B RAM.
footprint SOT129-1 (DIP, Plastic; 40 Leads; Row Spacing 15.24 mm; Pitch 2.54 mm)
pins: 1 P1.0/T2 (io), 2 P1.1/T2EX (io), 3 P1.2/ECI (io), 4 P1.3/CEX0 (io), 5 P1.4/CEX1 (io), 6 P1.5/CEX2 (io), 7 P1.6/CEX3 (io), 8 P1.7/CEX4 (io), 9 RST (in), 10 P3.0/RxD (io), 11 P3.1/TxD (io), 12 P3.2/~{INT}0 (io), 13 P3.3/~{INT}1 (io), 14 P3.4/T0 (io), 15 P3.5/T1 (io), 16 P3.6/~{WR} (io), 17 P3.7/~{RD} (io), 18 XTAL2 (out), 19 XTAL1 (in), 20 VSS (power), 21 P2.0/A8 (io), 22 P2.1/A9 (io), 23 P2.2/A10 (io), 24 P2.3/A11 (io), 25 P2.4/A12 (io), 26 P2.5/A13 (io), 27 P2.6/A14 (io), 28 P2.7/A15 (io), 29 ~{PSEN} (out), 30 ALE/~{PROG} (io), 31 ~{EA}/VPP (in), 32 P0.7/AD7 (io), 33 P0.6/AD6 (io), 34 P0.5/AD5 (io), 35 P0.4/AD4 (io), 36 P0.3/AD3 (io), 37 P0.2/AD2 (io), 38 P0.1/AD1 (io), 39 P0.0/AD0 (io), 40 VCC (power)

## P89C51RC2HFA
designator U?
80C51 8-Bit Flash Microcontroller Family, 32 kB ISP/IAP Flash with 512 B RAM.
footprint SOT187-2_N (Leaded Chip Carrier, 44-Leads, Body 16.6x16.6mm, Pitch 1.27mm, IPC Medium Density)
footprint SOT187-2_L (Leaded Chip Carrier, 44-Leads, Body 16.6x16.6mm, Pitch 1.27mm, IPC High Density)
footprint SOT187-2_M (Leaded Chip Carrier, 44-Leads, Body 16.6x16.6mm, Pitch 1.27mm, IPC Low Density)
pins: 1 NIC, 2 P1.0/T2 (io), 3 P1.1/T2EX (io), 4 P1.2/ECI (io), 5 P1.3/CEX0 (io), 6 P1.4/CEX1 (io), 7 P1.5/CEX2 (io), 8 P1.6/CEX3 (io), 9 P1.7/CEX4 (io), 10 RST (in), 11 P3.0/RxD (io), 12 NIC, 13 P3.1/TxD (io), 14 P3.2/~{INT}0 (io), 15 P3.3/~{INT}1 (io), 16 P3.4/T0 (io), 17 P3.5/T1 (io), 18 P3.6/~{WR} (io), 19 P3.7/~{RD} (io), 20 XTAL2 (out), 21 XTAL1 (in), 22 VSS (power), 23 NIC, 24 P2.0/A8 (io), 25 P2.1/A9 (io), 26 P2.2/A10 (io), 27 P2.3/A11 (io), 28 P2.4/A12 (io), 29 P2.5/A13 (io), 30 P2.6/A14 (io), 31 P2.7/A15 (io), 32 ~{PSEN} (out), 33 ALE/~{PROG} (io), 34 NIC, 35 ~{EA}/VPP (in), 36 P0.7/AD7 (io), 37 P0.6/AD6 (io), 38 P0.5/AD5 (io), 39 P0.4/AD4 (io), 40 P0.3/AD3 (io), 41 P0.2/AD2 (io), 42 P0.1/AD1 (io), 43 P0.0/AD0 (io), 44 VCC (power)

## P89C51RC2HFBD
designator U?
80C51 8-Bit Flash Microcontroller Family, 32 kB ISP/IAP Flash with 512 B RAM.
footprint SOT389-1_N (Thin QFP, 44-Leads, Body 10x10mm, Pitch 0.8mm, IPC Medium Density)
footprint SOT389-1_L (Thin QFP, 44-Leads, Body 10x10mm, Pitch 0.8mm, IPC High Density)
footprint SOT389-1_M (Thin QFP, 44-Leads, Body 10x10mm, Pitch 0.8mm, IPC Low Density)
pins: 1 P1.5/CEX2 (io), 2 P1.6/CEX3 (io), 3 P1.7/CEX4 (io), 4 RST (in), 5 P3.0/RxD (io), 6 NIC, 7 P3.1/TxD (io), 8 P3.2/~{INT}0 (io), 9 P3.3/~{INT}1 (io), 10 P3.4/T0 (io), 11 P3.5/T1 (io), 12 P3.6/~{WR} (io), 13 P3.7/~{RD} (io), 14 XTAL2 (out), 15 XTAL1 (in), 16 VSS (power), 17 NIC, 18 P2.0/A8 (io), 19 P2.1/A9 (io), 20 P2.2/A10 (io), 21 P2.3/A11 (io), 22 P2.4/A12 (io), 23 P2.5/A13 (io), 24 P2.6/A14 (io), 25 P2.7/A15 (io), 26 ~{PSEN} (out), 27 ALE/~{PROG} (io), 28 NIC, 29 ~{EA}/VPP (in), 30 P0.7/AD7 (io), 31 P0.6/AD6 (io), 32 P0.5/AD5 (io), 33 P0.4/AD4 (io), 34 P0.3/AD3 (io), 35 P0.2/AD2 (io), 36 P0.1/AD1 (io), 37 P0.0/AD0 (io), 38 VCC (power), 39 NIC, 40 P1.0/T2 (io), 41 P1.1/T2EX (io), 42 P1.2/ECI (io), 43 P1.3/CEX0 (io), 44 P1.4/CEX1 (io)

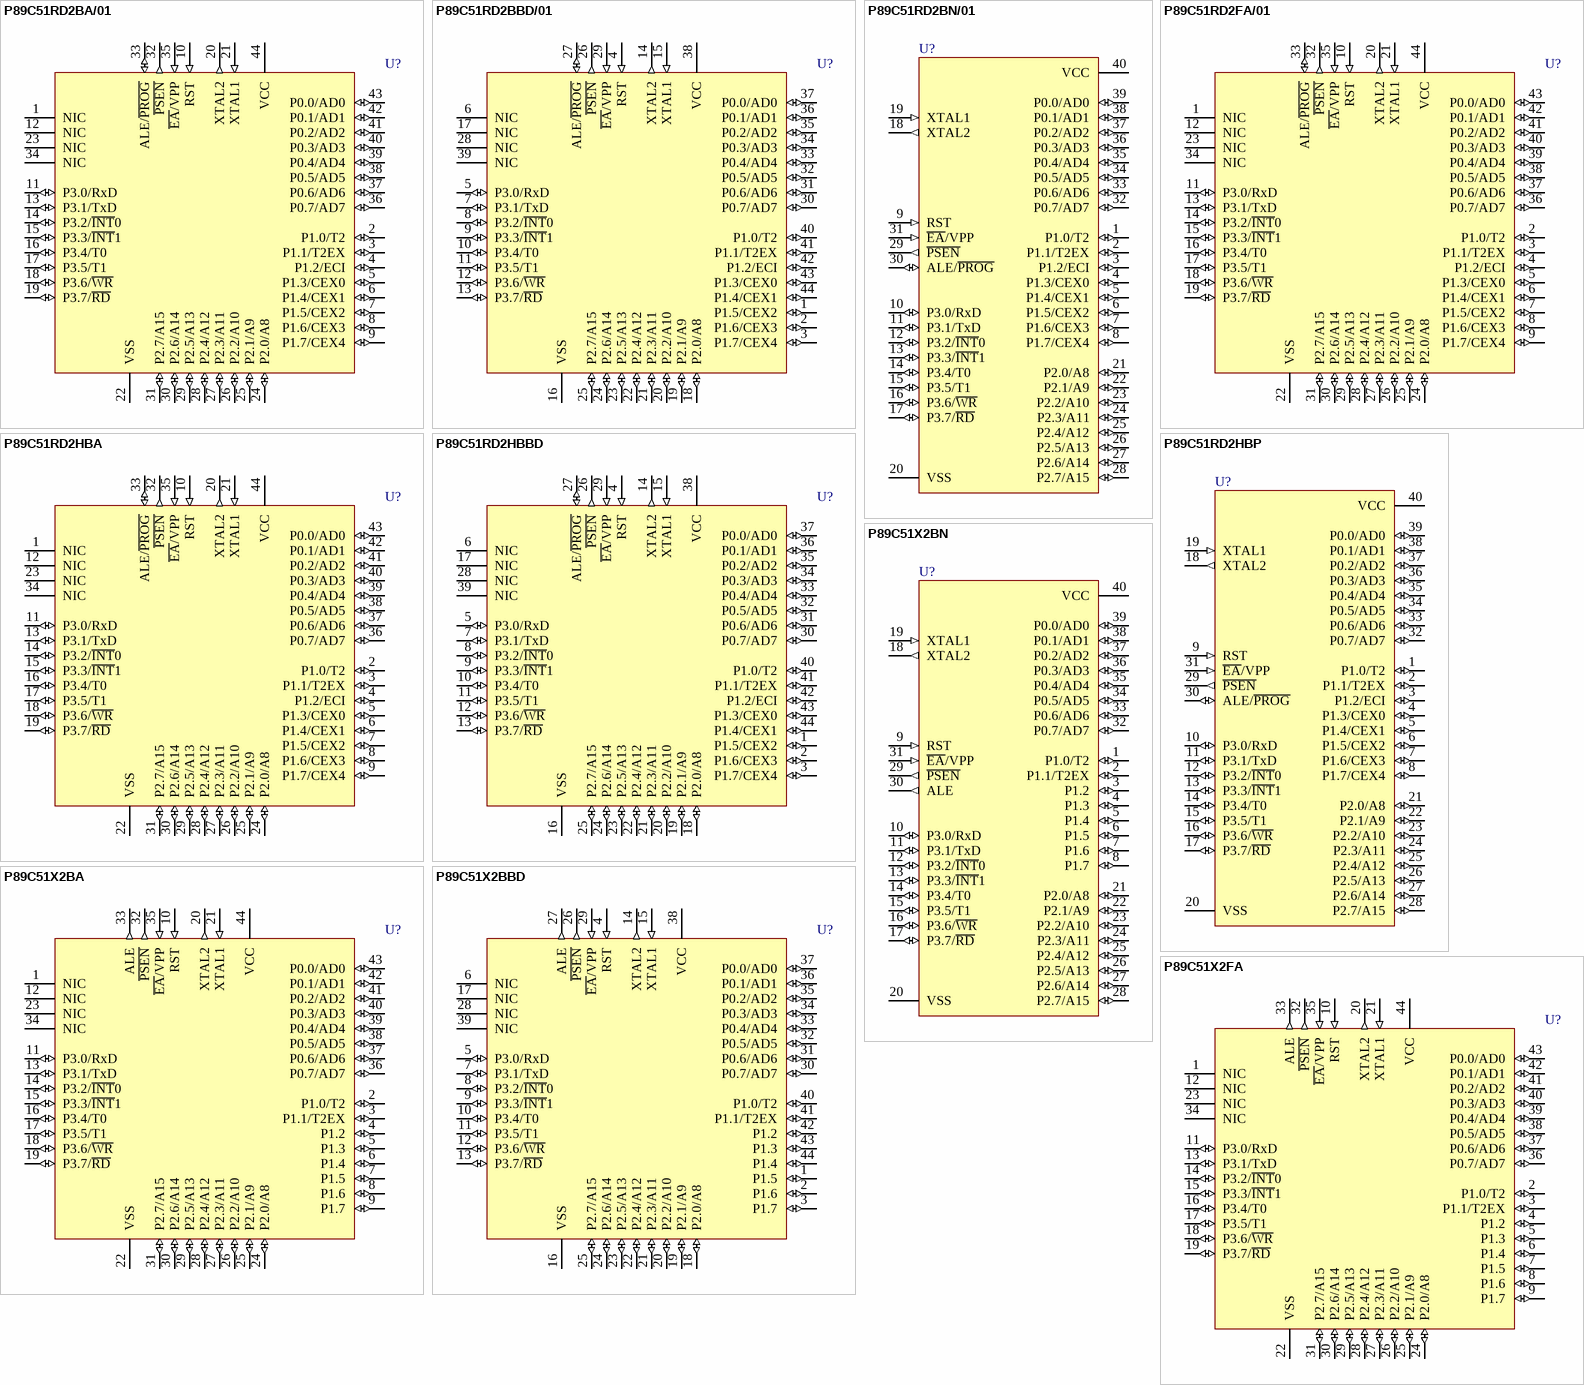
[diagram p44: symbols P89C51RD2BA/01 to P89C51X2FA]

## P89C51RD2BA/01
designator U?
80C51 8-Bit Flash Microcontroller Family, 64 kB ISP/IAP Flash with 1 kB RAM.
footprint SOT187-2_N (Leaded Chip Carrier, 44-Leads, Body 16.6x16.6mm, Pitch 1.27mm, IPC Medium Density)
footprint SOT187-2_L (Leaded Chip Carrier, 44-Leads, Body 16.6x16.6mm, Pitch 1.27mm, IPC High Density)
footprint SOT187-2_M (Leaded Chip Carrier, 44-Leads, Body 16.6x16.6mm, Pitch 1.27mm, IPC Low Density)
pins: 1 NIC, 2 P1.0/T2 (io), 3 P1.1/T2EX (io), 4 P1.2/ECI (io), 5 P1.3/CEX0 (io), 6 P1.4/CEX1 (io), 7 P1.5/CEX2 (io), 8 P1.6/CEX3 (io), 9 P1.7/CEX4 (io), 10 RST (in), 11 P3.0/RxD (io), 12 NIC, 13 P3.1/TxD (io), 14 P3.2/~{INT}0 (io), 15 P3.3/~{INT}1 (io), 16 P3.4/T0 (io), 17 P3.5/T1 (io), 18 P3.6/~{WR} (io), 19 P3.7/~{RD} (io), 20 XTAL2 (out), 21 XTAL1 (in), 22 VSS (power), 23 NIC, 24 P2.0/A8 (io), 25 P2.1/A9 (io), 26 P2.2/A10 (io), 27 P2.3/A11 (io), 28 P2.4/A12 (io), 29 P2.5/A13 (io), 30 P2.6/A14 (io), 31 P2.7/A15 (io), 32 ~{PSEN} (out), 33 ALE/~{PROG} (io), 34 NIC, 35 ~{EA}/VPP (in), 36 P0.7/AD7 (io), 37 P0.6/AD6 (io), 38 P0.5/AD5 (io), 39 P0.4/AD4 (io), 40 P0.3/AD3 (io), 41 P0.2/AD2 (io), 42 P0.1/AD1 (io), 43 P0.0/AD0 (io), 44 VCC (power)

## P89C51RD2BBD/01
designator U?
80C51 8-Bit Flash Microcontroller Family, 64 kB ISP/IAP Flash with 1 kB RAM.
footprint SOT389-1_N (Thin QFP, 44-Leads, Body 10x10mm, Pitch 0.8mm, IPC Medium Density)
footprint SOT389-1_L (Thin QFP, 44-Leads, Body 10x10mm, Pitch 0.8mm, IPC High Density)
footprint SOT389-1_M (Thin QFP, 44-Leads, Body 10x10mm, Pitch 0.8mm, IPC Low Density)
pins: 1 P1.5/CEX2 (io), 2 P1.6/CEX3 (io), 3 P1.7/CEX4 (io), 4 RST (in), 5 P3.0/RxD (io), 6 NIC, 7 P3.1/TxD (io), 8 P3.2/~{INT}0 (io), 9 P3.3/~{INT}1 (io), 10 P3.4/T0 (io), 11 P3.5/T1 (io), 12 P3.6/~{WR} (io), 13 P3.7/~{RD} (io), 14 XTAL2 (out), 15 XTAL1 (in), 16 VSS (power), 17 NIC, 18 P2.0/A8 (io), 19 P2.1/A9 (io), 20 P2.2/A10 (io), 21 P2.3/A11 (io), 22 P2.4/A12 (io), 23 P2.5/A13 (io), 24 P2.6/A14 (io), 25 P2.7/A15 (io), 26 ~{PSEN} (out), 27 ALE/~{PROG} (io), 28 NIC, 29 ~{EA}/VPP (in), 30 P0.7/AD7 (io), 31 P0.6/AD6 (io), 32 P0.5/AD5 (io), 33 P0.4/AD4 (io), 34 P0.3/AD3 (io), 35 P0.2/AD2 (io), 36 P0.1/AD1 (io), 37 P0.0/AD0 (io), 38 VCC (power), 39 NIC, 40 P1.0/T2 (io), 41 P1.1/T2EX (io), 42 P1.2/ECI (io), 43 P1.3/CEX0 (io), 44 P1.4/CEX1 (io)

## P89C51RD2BN/01
designator U?
80C51 8-Bit Flash Microcontroller Family, 64 kB ISP/IAP Flash with 1 kB RAM.
footprint SOT129-1 (DIP, Plastic; 40 Leads; Row Spacing 15.24 mm; Pitch 2.54 mm)
pins: 1 P1.0/T2 (io), 2 P1.1/T2EX (io), 3 P1.2/ECI (io), 4 P1.3/CEX0 (io), 5 P1.4/CEX1 (io), 6 P1.5/CEX2 (io), 7 P1.6/CEX3 (io), 8 P1.7/CEX4 (io), 9 RST (in), 10 P3.0/RxD (io), 11 P3.1/TxD (io), 12 P3.2/~{INT}0 (io), 13 P3.3/~{INT}1 (io), 14 P3.4/T0 (io), 15 P3.5/T1 (io), 16 P3.6/~{WR} (io), 17 P3.7/~{RD} (io), 18 XTAL2 (out), 19 XTAL1 (in), 20 VSS (power), 21 P2.0/A8 (io), 22 P2.1/A9 (io), 23 P2.2/A10 (io), 24 P2.3/A11 (io), 25 P2.4/A12 (io), 26 P2.5/A13 (io), 27 P2.6/A14 (io), 28 P2.7/A15 (io), 29 ~{PSEN} (out), 30 ALE/~{PROG} (io), 31 ~{EA}/VPP (in), 32 P0.7/AD7 (io), 33 P0.6/AD6 (io), 34 P0.5/AD5 (io), 35 P0.4/AD4 (io), 36 P0.3/AD3 (io), 37 P0.2/AD2 (io), 38 P0.1/AD1 (io), 39 P0.0/AD0 (io), 40 VCC (power)

## P89C51RD2FA/01
designator U?
80C51 8-Bit Flash Microcontroller Family, 64 kB ISP/IAP Flash with 1 kB RAM.
footprint SOT187-2_N (Leaded Chip Carrier, 44-Leads, Body 16.6x16.6mm, Pitch 1.27mm, IPC Medium Density)
footprint SOT187-2_L (Leaded Chip Carrier, 44-Leads, Body 16.6x16.6mm, Pitch 1.27mm, IPC High Density)
footprint SOT187-2_M (Leaded Chip Carrier, 44-Leads, Body 16.6x16.6mm, Pitch 1.27mm, IPC Low Density)
pins: 1 NIC, 2 P1.0/T2 (io), 3 P1.1/T2EX (io), 4 P1.2/ECI (io), 5 P1.3/CEX0 (io), 6 P1.4/CEX1 (io), 7 P1.5/CEX2 (io), 8 P1.6/CEX3 (io), 9 P1.7/CEX4 (io), 10 RST (in), 11 P3.0/RxD (io), 12 NIC, 13 P3.1/TxD (io), 14 P3.2/~{INT}0 (io), 15 P3.3/~{INT}1 (io), 16 P3.4/T0 (io), 17 P3.5/T1 (io), 18 P3.6/~{WR} (io), 19 P3.7/~{RD} (io), 20 XTAL2 (out), 21 XTAL1 (in), 22 VSS (power), 23 NIC, 24 P2.0/A8 (io), 25 P2.1/A9 (io), 26 P2.2/A10 (io), 27 P2.3/A11 (io), 28 P2.4/A12 (io), 29 P2.5/A13 (io), 30 P2.6/A14 (io), 31 P2.7/A15 (io), 32 ~{PSEN} (out), 33 ALE/~{PROG} (io), 34 NIC, 35 ~{EA}/VPP (in), 36 P0.7/AD7 (io), 37 P0.6/AD6 (io), 38 P0.5/AD5 (io), 39 P0.4/AD4 (io), 40 P0.3/AD3 (io), 41 P0.2/AD2 (io), 42 P0.1/AD1 (io), 43 P0.0/AD0 (io), 44 VCC (power)

## P89C51RD2HBA
designator U?
80C51 8-Bit Flash Microcontroller Family, 64 kB ISP/IAP Flash with 1 kB RAM.
footprint SOT187-2_N (Leaded Chip Carrier, 44-Leads, Body 16.6x16.6mm, Pitch 1.27mm, IPC Medium Density)
footprint SOT187-2_L (Leaded Chip Carrier, 44-Leads, Body 16.6x16.6mm, Pitch 1.27mm, IPC High Density)
footprint SOT187-2_M (Leaded Chip Carrier, 44-Leads, Body 16.6x16.6mm, Pitch 1.27mm, IPC Low Density)
pins: 1 NIC, 2 P1.0/T2 (io), 3 P1.1/T2EX (io), 4 P1.2/ECI (io), 5 P1.3/CEX0 (io), 6 P1.4/CEX1 (io), 7 P1.5/CEX2 (io), 8 P1.6/CEX3 (io), 9 P1.7/CEX4 (io), 10 RST (in), 11 P3.0/RxD (io), 12 NIC, 13 P3.1/TxD (io), 14 P3.2/~{INT}0 (io), 15 P3.3/~{INT}1 (io), 16 P3.4/T0 (io), 17 P3.5/T1 (io), 18 P3.6/~{WR} (io), 19 P3.7/~{RD} (io), 20 XTAL2 (out), 21 XTAL1 (in), 22 VSS (power), 23 NIC, 24 P2.0/A8 (io), 25 P2.1/A9 (io), 26 P2.2/A10 (io), 27 P2.3/A11 (io), 28 P2.4/A12 (io), 29 P2.5/A13 (io), 30 P2.6/A14 (io), 31 P2.7/A15 (io), 32 ~{PSEN} (out), 33 ALE/~{PROG} (io), 34 NIC, 35 ~{EA}/VPP (in), 36 P0.7/AD7 (io), 37 P0.6/AD6 (io), 38 P0.5/AD5 (io), 39 P0.4/AD4 (io), 40 P0.3/AD3 (io), 41 P0.2/AD2 (io), 42 P0.1/AD1 (io), 43 P0.0/AD0 (io), 44 VCC (power)

## P89C51RD2HBBD
designator U?
80C51 8-Bit Flash Microcontroller Family, 64 kB ISP/IAP Flash with 1 kB RAM.
footprint SOT389-1_N (Thin QFP, 44-Leads, Body 10x10mm, Pitch 0.8mm, IPC Medium Density)
footprint SOT389-1_L (Thin QFP, 44-Leads, Body 10x10mm, Pitch 0.8mm, IPC High Density)
footprint SOT389-1_M (Thin QFP, 44-Leads, Body 10x10mm, Pitch 0.8mm, IPC Low Density)
pins: 1 P1.5/CEX2 (io), 2 P1.6/CEX3 (io), 3 P1.7/CEX4 (io), 4 RST (in), 5 P3.0/RxD (io), 6 NIC, 7 P3.1/TxD (io), 8 P3.2/~{INT}0 (io), 9 P3.3/~{INT}1 (io), 10 P3.4/T0 (io), 11 P3.5/T1 (io), 12 P3.6/~{WR} (io), 13 P3.7/~{RD} (io), 14 XTAL2 (out), 15 XTAL1 (in), 16 VSS (power), 17 NIC, 18 P2.0/A8 (io), 19 P2.1/A9 (io), 20 P2.2/A10 (io), 21 P2.3/A11 (io), 22 P2.4/A12 (io), 23 P2.5/A13 (io), 24 P2.6/A14 (io), 25 P2.7/A15 (io), 26 ~{PSEN} (out), 27 ALE/~{PROG} (io), 28 NIC, 29 ~{EA}/VPP (in), 30 P0.7/AD7 (io), 31 P0.6/AD6 (io), 32 P0.5/AD5 (io), 33 P0.4/AD4 (io), 34 P0.3/AD3 (io), 35 P0.2/AD2 (io), 36 P0.1/AD1 (io), 37 P0.0/AD0 (io), 38 VCC (power), 39 NIC, 40 P1.0/T2 (io), 41 P1.1/T2EX (io), 42 P1.2/ECI (io), 43 P1.3/CEX0 (io), 44 P1.4/CEX1 (io)

## P89C51RD2HBP
designator U?
80C51 8-Bit Flash Microcontroller Family, 64 kB ISP/IAP Flash with 1 kB RAM.
footprint SOT129-1 (DIP, Plastic; 40 Leads; Row Spacing 15.24 mm; Pitch 2.54 mm)
pins: 1 P1.0/T2 (io), 2 P1.1/T2EX (io), 3 P1.2/ECI (io), 4 P1.3/CEX0 (io), 5 P1.4/CEX1 (io), 6 P1.5/CEX2 (io), 7 P1.6/CEX3 (io), 8 P1.7/CEX4 (io), 9 RST (in), 10 P3.0/RxD (io), 11 P3.1/TxD (io), 12 P3.2/~{INT}0 (io), 13 P3.3/~{INT}1 (io), 14 P3.4/T0 (io), 15 P3.5/T1 (io), 16 P3.6/~{WR} (io), 17 P3.7/~{RD} (io), 18 XTAL2 (out), 19 XTAL1 (in), 20 VSS (power), 21 P2.0/A8 (io), 22 P2.1/A9 (io), 23 P2.2/A10 (io), 24 P2.3/A11 (io), 25 P2.4/A12 (io), 26 P2.5/A13 (io), 27 P2.6/A14 (io), 28 P2.7/A15 (io), 29 ~{PSEN} (out), 30 ALE/~{PROG} (io), 31 ~{EA}/VPP (in), 32 P0.7/AD7 (io), 33 P0.6/AD6 (io), 34 P0.5/AD5 (io), 35 P0.4/AD4 (io), 36 P0.3/AD3 (io), 37 P0.2/AD2 (io), 38 P0.1/AD1 (io), 39 P0.0/AD0 (io), 40 VCC (power)

## P89C51X2BA
designator U?
80C51 8-Bit Flash Microcontroller Family, 4 kB Flash
footprint SOT187-2_N (Leaded Chip Carrier, 44-Leads, Body 16.6x16.6mm, Pitch 1.27mm, IPC Medium Density)
footprint SOT187-2_L (Leaded Chip Carrier, 44-Leads, Body 16.6x16.6mm, Pitch 1.27mm, IPC High Density)
footprint SOT187-2_M (Leaded Chip Carrier, 44-Leads, Body 16.6x16.6mm, Pitch 1.27mm, IPC Low Density)
pins: 1 NIC, 2 P1.0/T2 (io), 3 P1.1/T2EX (io), 4 P1.2 (io), 5 P1.3 (io), 6 P1.4 (io), 7 P1.5 (io), 8 P1.6 (io), 9 P1.7 (io), 10 RST (in), 11 P3.0/RxD (io), 12 NIC, 13 P3.1/TxD (io), 14 P3.2/~{INT}0 (io), 15 P3.3/~{INT}1 (io), 16 P3.4/T0 (io), 17 P3.5/T1 (io), 18 P3.6/~{WR} (io), 19 P3.7/~{RD} (io), 20 XTAL2 (out), 21 XTAL1 (in), 22 VSS (power), 23 NIC, 24 P2.0/A8 (io), 25 P2.1/A9 (io), 26 P2.2/A10 (io), 27 P2.3/A11 (io), 28 P2.4/A12 (io), 29 P2.5/A13 (io), 30 P2.6/A14 (io), 31 P2.7/A15 (io), 32 ~{PSEN} (out), 33 ALE (out), 34 NIC, 35 ~{EA}/VPP (in), 36 P0.7/AD7 (io), 37 P0.6/AD6 (io), 38 P0.5/AD5 (io), 39 P0.4/AD4 (io), 40 P0.3/AD3 (io), 41 P0.2/AD2 (io), 42 P0.1/AD1 (io), 43 P0.0/AD0 (io), 44 VCC (power)

## P89C51X2BBD
designator U?
80C51 8-Bit Flash Microcontroller Family, 4 kB Flash
footprint SOT389-1_N (Thin QFP, 44-Leads, Body 10x10mm, Pitch 0.8mm, IPC Medium Density)
footprint SOT389-1_L (Thin QFP, 44-Leads, Body 10x10mm, Pitch 0.8mm, IPC High Density)
footprint SOT389-1_M (Thin QFP, 44-Leads, Body 10x10mm, Pitch 0.8mm, IPC Low Density)
pins: 1 P1.5 (io), 2 P1.6 (io), 3 P1.7 (io), 4 RST (in), 5 P3.0/RxD (io), 6 NIC, 7 P3.1/TxD (io), 8 P3.2/~{INT}0 (io), 9 P3.3/~{INT}1 (io), 10 P3.4/T0 (io), 11 P3.5/T1 (io), 12 P3.6/~{WR} (io), 13 P3.7/~{RD} (io), 14 XTAL2 (out), 15 XTAL1 (in), 16 VSS (power), 17 NIC, 18 P2.0/A8 (io), 19 P2.1/A9 (io), 20 P2.2/A10 (io), 21 P2.3/A11 (io), 22 P2.4/A12 (io), 23 P2.5/A13 (io), 24 P2.6/A14 (io), 25 P2.7/A15 (io), 26 ~{PSEN} (out), 27 ALE (out), 28 NIC, 29 ~{EA}/VPP (in), 30 P0.7/AD7 (io), 31 P0.6/AD6 (io), 32 P0.5/AD5 (io), 33 P0.4/AD4 (io), 34 P0.3/AD3 (io), 35 P0.2/AD2 (io), 36 P0.1/AD1 (io), 37 P0.0/AD0 (io), 38 VCC (power), 39 NIC, 40 P1.0/T2 (io), 41 P1.1/T2EX (io), 42 P1.2 (io), 43 P1.3 (io), 44 P1.4 (io)

## P89C51X2BN
designator U?
80C51 8-Bit Flash Microcontroller Family, 4 kB Flash
footprint SOT129-1 (DIP, Plastic; 40 Leads; Row Spacing 15.24 mm; Pitch 2.54 mm)
pins: 1 P1.0/T2 (io), 2 P1.1/T2EX (io), 3 P1.2 (io), 4 P1.3 (io), 5 P1.4 (io), 6 P1.5 (io), 7 P1.6 (io), 8 P1.7 (io), 9 RST (in), 10 P3.0/RxD (io), 11 P3.1/TxD (io), 12 P3.2/~{INT}0 (io), 13 P3.3/~{INT}1 (io), 14 P3.4/T0 (io), 15 P3.5/T1 (io), 16 P3.6/~{WR} (io), 17 P3.7/~{RD} (io), 18 XTAL2 (out), 19 XTAL1 (in), 20 VSS (power), 21 P2.0/A8 (io), 22 P2.1/A9 (io), 23 P2.2/A10 (io), 24 P2.3/A11 (io), 25 P2.4/A12 (io), 26 P2.5/A13 (io), 27 P2.6/A14 (io), 28 P2.7/A15 (io), 29 ~{PSEN} (out), 30 ALE (out), 31 ~{EA}/VPP (in), 32 P0.7/AD7 (io), 33 P0.6/AD6 (io), 34 P0.5/AD5 (io), 35 P0.4/AD4 (io), 36 P0.3/AD3 (io), 37 P0.2/AD2 (io), 38 P0.1/AD1 (io), 39 P0.0/AD0 (io), 40 VCC (power)

## P89C51X2FA
designator U?
80C51 8-Bit Flash Microcontroller Family, 4 kB Flash
footprint SOT187-2_N (Leaded Chip Carrier, 44-Leads, Body 16.6x16.6mm, Pitch 1.27mm, IPC Medium Density)
footprint SOT187-2_L (Leaded Chip Carrier, 44-Leads, Body 16.6x16.6mm, Pitch 1.27mm, IPC High Density)
footprint SOT187-2_M (Leaded Chip Carrier, 44-Leads, Body 16.6x16.6mm, Pitch 1.27mm, IPC Low Density)
pins: 1 NIC, 2 P1.0/T2 (io), 3 P1.1/T2EX (io), 4 P1.2 (io), 5 P1.3 (io), 6 P1.4 (io), 7 P1.5 (io), 8 P1.6 (io), 9 P1.7 (io), 10 RST (in), 11 P3.0/RxD (io), 12 NIC, 13 P3.1/TxD (io), 14 P3.2/~{INT}0 (io), 15 P3.3/~{INT}1 (io), 16 P3.4/T0 (io), 17 P3.5/T1 (io), 18 P3.6/~{WR} (io), 19 P3.7/~{RD} (io), 20 XTAL2 (out), 21 XTAL1 (in), 22 VSS (power), 23 NIC, 24 P2.0/A8 (io), 25 P2.1/A9 (io), 26 P2.2/A10 (io), 27 P2.3/A11 (io), 28 P2.4/A12 (io), 29 P2.5/A13 (io), 30 P2.6/A14 (io), 31 P2.7/A15 (io), 32 ~{PSEN} (out), 33 ALE (out), 34 NIC, 35 ~{EA}/VPP (in), 36 P0.7/AD7 (io), 37 P0.6/AD6 (io), 38 P0.5/AD5 (io), 39 P0.4/AD4 (io), 40 P0.3/AD3 (io), 41 P0.2/AD2 (io), 42 P0.1/AD1 (io), 43 P0.0/AD0 (io), 44 VCC (power)

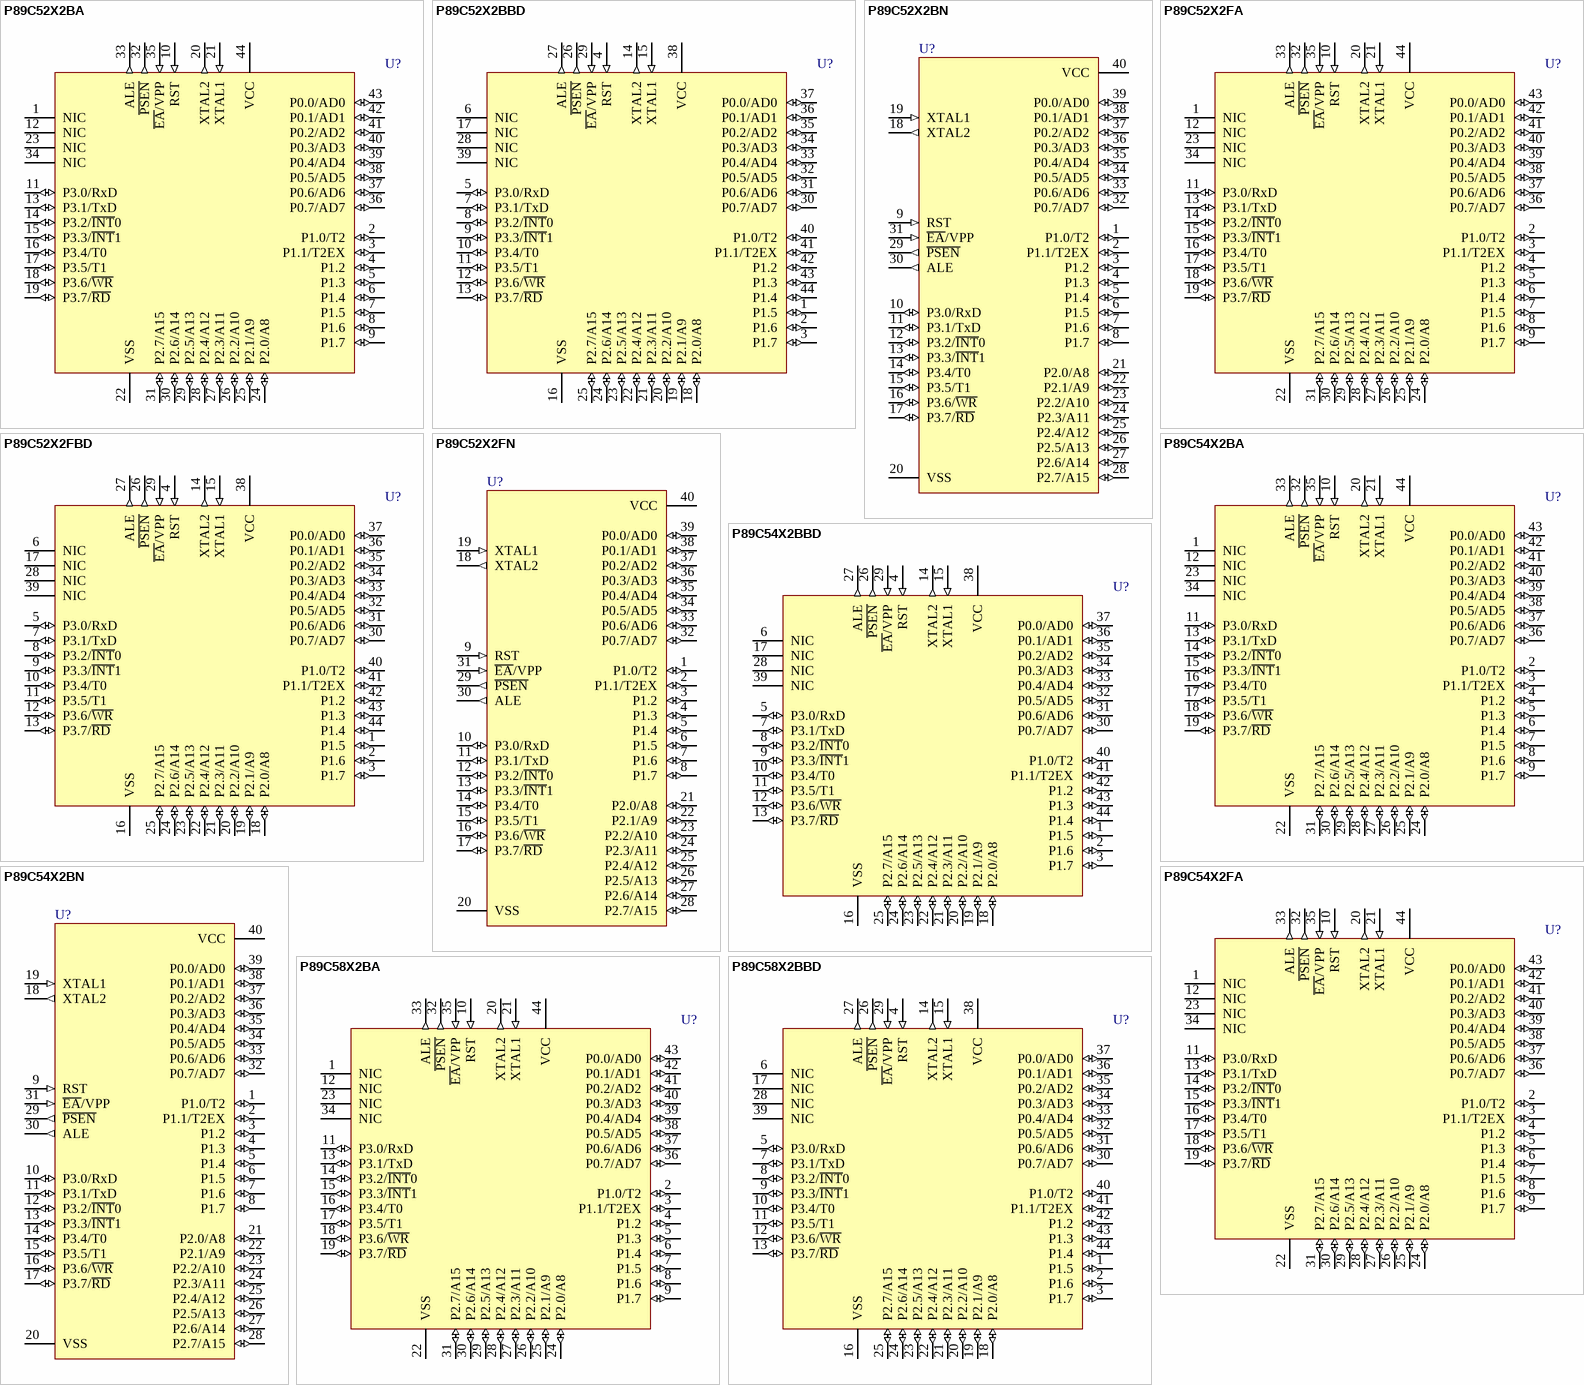
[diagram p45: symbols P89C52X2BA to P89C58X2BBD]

## P89C52X2BA
designator U?
80C51 8-Bit Flash Microcontroller Family, 8 kB Flash
footprint SOT187-2_N (Leaded Chip Carrier, 44-Leads, Body 16.6x16.6mm, Pitch 1.27mm, IPC Medium Density)
footprint SOT187-2_L (Leaded Chip Carrier, 44-Leads, Body 16.6x16.6mm, Pitch 1.27mm, IPC High Density)
footprint SOT187-2_M (Leaded Chip Carrier, 44-Leads, Body 16.6x16.6mm, Pitch 1.27mm, IPC Low Density)
pins: 1 NIC, 2 P1.0/T2 (io), 3 P1.1/T2EX (io), 4 P1.2 (io), 5 P1.3 (io), 6 P1.4 (io), 7 P1.5 (io), 8 P1.6 (io), 9 P1.7 (io), 10 RST (in), 11 P3.0/RxD (io), 12 NIC, 13 P3.1/TxD (io), 14 P3.2/~{INT}0 (io), 15 P3.3/~{INT}1 (io), 16 P3.4/T0 (io), 17 P3.5/T1 (io), 18 P3.6/~{WR} (io), 19 P3.7/~{RD} (io), 20 XTAL2 (out), 21 XTAL1 (in), 22 VSS (power), 23 NIC, 24 P2.0/A8 (io), 25 P2.1/A9 (io), 26 P2.2/A10 (io), 27 P2.3/A11 (io), 28 P2.4/A12 (io), 29 P2.5/A13 (io), 30 P2.6/A14 (io), 31 P2.7/A15 (io), 32 ~{PSEN} (out), 33 ALE (out), 34 NIC, 35 ~{EA}/VPP (in), 36 P0.7/AD7 (io), 37 P0.6/AD6 (io), 38 P0.5/AD5 (io), 39 P0.4/AD4 (io), 40 P0.3/AD3 (io), 41 P0.2/AD2 (io), 42 P0.1/AD1 (io), 43 P0.0/AD0 (io), 44 VCC (power)

## P89C52X2BBD
designator U?
80C51 8-Bit Flash Microcontroller Family, 8 kB Flash
footprint SOT389-1_N (Thin QFP, 44-Leads, Body 10x10mm, Pitch 0.8mm, IPC Medium Density)
footprint SOT389-1_L (Thin QFP, 44-Leads, Body 10x10mm, Pitch 0.8mm, IPC High Density)
footprint SOT389-1_M (Thin QFP, 44-Leads, Body 10x10mm, Pitch 0.8mm, IPC Low Density)
pins: 1 P1.5 (io), 2 P1.6 (io), 3 P1.7 (io), 4 RST (in), 5 P3.0/RxD (io), 6 NIC, 7 P3.1/TxD (io), 8 P3.2/~{INT}0 (io), 9 P3.3/~{INT}1 (io), 10 P3.4/T0 (io), 11 P3.5/T1 (io), 12 P3.6/~{WR} (io), 13 P3.7/~{RD} (io), 14 XTAL2 (out), 15 XTAL1 (in), 16 VSS (power), 17 NIC, 18 P2.0/A8 (io), 19 P2.1/A9 (io), 20 P2.2/A10 (io), 21 P2.3/A11 (io), 22 P2.4/A12 (io), 23 P2.5/A13 (io), 24 P2.6/A14 (io), 25 P2.7/A15 (io), 26 ~{PSEN} (out), 27 ALE (out), 28 NIC, 29 ~{EA}/VPP (in), 30 P0.7/AD7 (io), 31 P0.6/AD6 (io), 32 P0.5/AD5 (io), 33 P0.4/AD4 (io), 34 P0.3/AD3 (io), 35 P0.2/AD2 (io), 36 P0.1/AD1 (io), 37 P0.0/AD0 (io), 38 VCC (power), 39 NIC, 40 P1.0/T2 (io), 41 P1.1/T2EX (io), 42 P1.2 (io), 43 P1.3 (io), 44 P1.4 (io)

## P89C52X2BN
designator U?
80C51 8-Bit Flash Microcontroller Family, 8 kB Flash
footprint SOT129-1 (DIP, Plastic; 40 Leads; Row Spacing 15.24 mm; Pitch 2.54 mm)
pins: 1 P1.0/T2 (io), 2 P1.1/T2EX (io), 3 P1.2 (io), 4 P1.3 (io), 5 P1.4 (io), 6 P1.5 (io), 7 P1.6 (io), 8 P1.7 (io), 9 RST (in), 10 P3.0/RxD (io), 11 P3.1/TxD (io), 12 P3.2/~{INT}0 (io), 13 P3.3/~{INT}1 (io), 14 P3.4/T0 (io), 15 P3.5/T1 (io), 16 P3.6/~{WR} (io), 17 P3.7/~{RD} (io), 18 XTAL2 (out), 19 XTAL1 (in), 20 VSS (power), 21 P2.0/A8 (io), 22 P2.1/A9 (io), 23 P2.2/A10 (io), 24 P2.3/A11 (io), 25 P2.4/A12 (io), 26 P2.5/A13 (io), 27 P2.6/A14 (io), 28 P2.7/A15 (io), 29 ~{PSEN} (out), 30 ALE (out), 31 ~{EA}/VPP (in), 32 P0.7/AD7 (io), 33 P0.6/AD6 (io), 34 P0.5/AD5 (io), 35 P0.4/AD4 (io), 36 P0.3/AD3 (io), 37 P0.2/AD2 (io), 38 P0.1/AD1 (io), 39 P0.0/AD0 (io), 40 VCC (power)

## P89C52X2FA
designator U?
80C51 8-Bit Flash Microcontroller Family, 8 kB Flash
footprint SOT187-2_N (Leaded Chip Carrier, 44-Leads, Body 16.6x16.6mm, Pitch 1.27mm, IPC Medium Density)
footprint SOT187-2_L (Leaded Chip Carrier, 44-Leads, Body 16.6x16.6mm, Pitch 1.27mm, IPC High Density)
footprint SOT187-2_M (Leaded Chip Carrier, 44-Leads, Body 16.6x16.6mm, Pitch 1.27mm, IPC Low Density)
pins: 1 NIC, 2 P1.0/T2 (io), 3 P1.1/T2EX (io), 4 P1.2 (io), 5 P1.3 (io), 6 P1.4 (io), 7 P1.5 (io), 8 P1.6 (io), 9 P1.7 (io), 10 RST (in), 11 P3.0/RxD (io), 12 NIC, 13 P3.1/TxD (io), 14 P3.2/~{INT}0 (io), 15 P3.3/~{INT}1 (io), 16 P3.4/T0 (io), 17 P3.5/T1 (io), 18 P3.6/~{WR} (io), 19 P3.7/~{RD} (io), 20 XTAL2 (out), 21 XTAL1 (in), 22 VSS (power), 23 NIC, 24 P2.0/A8 (io), 25 P2.1/A9 (io), 26 P2.2/A10 (io), 27 P2.3/A11 (io), 28 P2.4/A12 (io), 29 P2.5/A13 (io), 30 P2.6/A14 (io), 31 P2.7/A15 (io), 32 ~{PSEN} (out), 33 ALE (out), 34 NIC, 35 ~{EA}/VPP (in), 36 P0.7/AD7 (io), 37 P0.6/AD6 (io), 38 P0.5/AD5 (io), 39 P0.4/AD4 (io), 40 P0.3/AD3 (io), 41 P0.2/AD2 (io), 42 P0.1/AD1 (io), 43 P0.0/AD0 (io), 44 VCC (power)

## P89C52X2FBD
designator U?
80C51 8-Bit Flash Microcontroller Family, 8 kB Flash
footprint SOT389-1_N (Thin QFP, 44-Leads, Body 10x10mm, Pitch 0.8mm, IPC Medium Density)
footprint SOT389-1_L (Thin QFP, 44-Leads, Body 10x10mm, Pitch 0.8mm, IPC High Density)
footprint SOT389-1_M (Thin QFP, 44-Leads, Body 10x10mm, Pitch 0.8mm, IPC Low Density)
pins: 1 P1.5 (io), 2 P1.6 (io), 3 P1.7 (io), 4 RST (in), 5 P3.0/RxD (io), 6 NIC, 7 P3.1/TxD (io), 8 P3.2/~{INT}0 (io), 9 P3.3/~{INT}1 (io), 10 P3.4/T0 (io), 11 P3.5/T1 (io), 12 P3.6/~{WR} (io), 13 P3.7/~{RD} (io), 14 XTAL2 (out), 15 XTAL1 (in), 16 VSS (power), 17 NIC, 18 P2.0/A8 (io), 19 P2.1/A9 (io), 20 P2.2/A10 (io), 21 P2.3/A11 (io), 22 P2.4/A12 (io), 23 P2.5/A13 (io), 24 P2.6/A14 (io), 25 P2.7/A15 (io), 26 ~{PSEN} (out), 27 ALE (out), 28 NIC, 29 ~{EA}/VPP (in), 30 P0.7/AD7 (io), 31 P0.6/AD6 (io), 32 P0.5/AD5 (io), 33 P0.4/AD4 (io), 34 P0.3/AD3 (io), 35 P0.2/AD2 (io), 36 P0.1/AD1 (io), 37 P0.0/AD0 (io), 38 VCC (power), 39 NIC, 40 P1.0/T2 (io), 41 P1.1/T2EX (io), 42 P1.2 (io), 43 P1.3 (io), 44 P1.4 (io)

## P89C52X2FN
designator U?
80C51 8-Bit Flash Microcontroller Family, 8 kB Flash
footprint SOT129-1 (DIP, Plastic; 40 Leads; Row Spacing 15.24 mm; Pitch 2.54 mm)
pins: 1 P1.0/T2 (io), 2 P1.1/T2EX (io), 3 P1.2 (io), 4 P1.3 (io), 5 P1.4 (io), 6 P1.5 (io), 7 P1.6 (io), 8 P1.7 (io), 9 RST (in), 10 P3.0/RxD (io), 11 P3.1/TxD (io), 12 P3.2/~{INT}0 (io), 13 P3.3/~{INT}1 (io), 14 P3.4/T0 (io), 15 P3.5/T1 (io), 16 P3.6/~{WR} (io), 17 P3.7/~{RD} (io), 18 XTAL2 (out), 19 XTAL1 (in), 20 VSS (power), 21 P2.0/A8 (io), 22 P2.1/A9 (io), 23 P2.2/A10 (io), 24 P2.3/A11 (io), 25 P2.4/A12 (io), 26 P2.5/A13 (io), 27 P2.6/A14 (io), 28 P2.7/A15 (io), 29 ~{PSEN} (out), 30 ALE (out), 31 ~{EA}/VPP (in), 32 P0.7/AD7 (io), 33 P0.6/AD6 (io), 34 P0.5/AD5 (io), 35 P0.4/AD4 (io), 36 P0.3/AD3 (io), 37 P0.2/AD2 (io), 38 P0.1/AD1 (io), 39 P0.0/AD0 (io), 40 VCC (power)

## P89C54X2BA
designator U?
80C51 8-Bit Flash Microcontroller Family, 16 kB Flash
footprint SOT187-2_N (Leaded Chip Carrier, 44-Leads, Body 16.6x16.6mm, Pitch 1.27mm, IPC Medium Density)
footprint SOT187-2_L (Leaded Chip Carrier, 44-Leads, Body 16.6x16.6mm, Pitch 1.27mm, IPC High Density)
footprint SOT187-2_M (Leaded Chip Carrier, 44-Leads, Body 16.6x16.6mm, Pitch 1.27mm, IPC Low Density)
pins: 1 NIC, 2 P1.0/T2 (io), 3 P1.1/T2EX (io), 4 P1.2 (io), 5 P1.3 (io), 6 P1.4 (io), 7 P1.5 (io), 8 P1.6 (io), 9 P1.7 (io), 10 RST (in), 11 P3.0/RxD (io), 12 NIC, 13 P3.1/TxD (io), 14 P3.2/~{INT}0 (io), 15 P3.3/~{INT}1 (io), 16 P3.4/T0 (io), 17 P3.5/T1 (io), 18 P3.6/~{WR} (io), 19 P3.7/~{RD} (io), 20 XTAL2 (out), 21 XTAL1 (in), 22 VSS (power), 23 NIC, 24 P2.0/A8 (io), 25 P2.1/A9 (io), 26 P2.2/A10 (io), 27 P2.3/A11 (io), 28 P2.4/A12 (io), 29 P2.5/A13 (io), 30 P2.6/A14 (io), 31 P2.7/A15 (io), 32 ~{PSEN} (out), 33 ALE (out), 34 NIC, 35 ~{EA}/VPP (in), 36 P0.7/AD7 (io), 37 P0.6/AD6 (io), 38 P0.5/AD5 (io), 39 P0.4/AD4 (io), 40 P0.3/AD3 (io), 41 P0.2/AD2 (io), 42 P0.1/AD1 (io), 43 P0.0/AD0 (io), 44 VCC (power)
